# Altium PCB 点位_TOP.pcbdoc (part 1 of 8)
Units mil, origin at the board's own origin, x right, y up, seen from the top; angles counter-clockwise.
Board outline 5129 x 4161 mil, 8 copper layers (Top Layer, GND1, 内层2, VCC, 内层4, Inner5, GND2, Bottom Layer); 288 components, 452 nets, 2040 pads, 1119 vias.
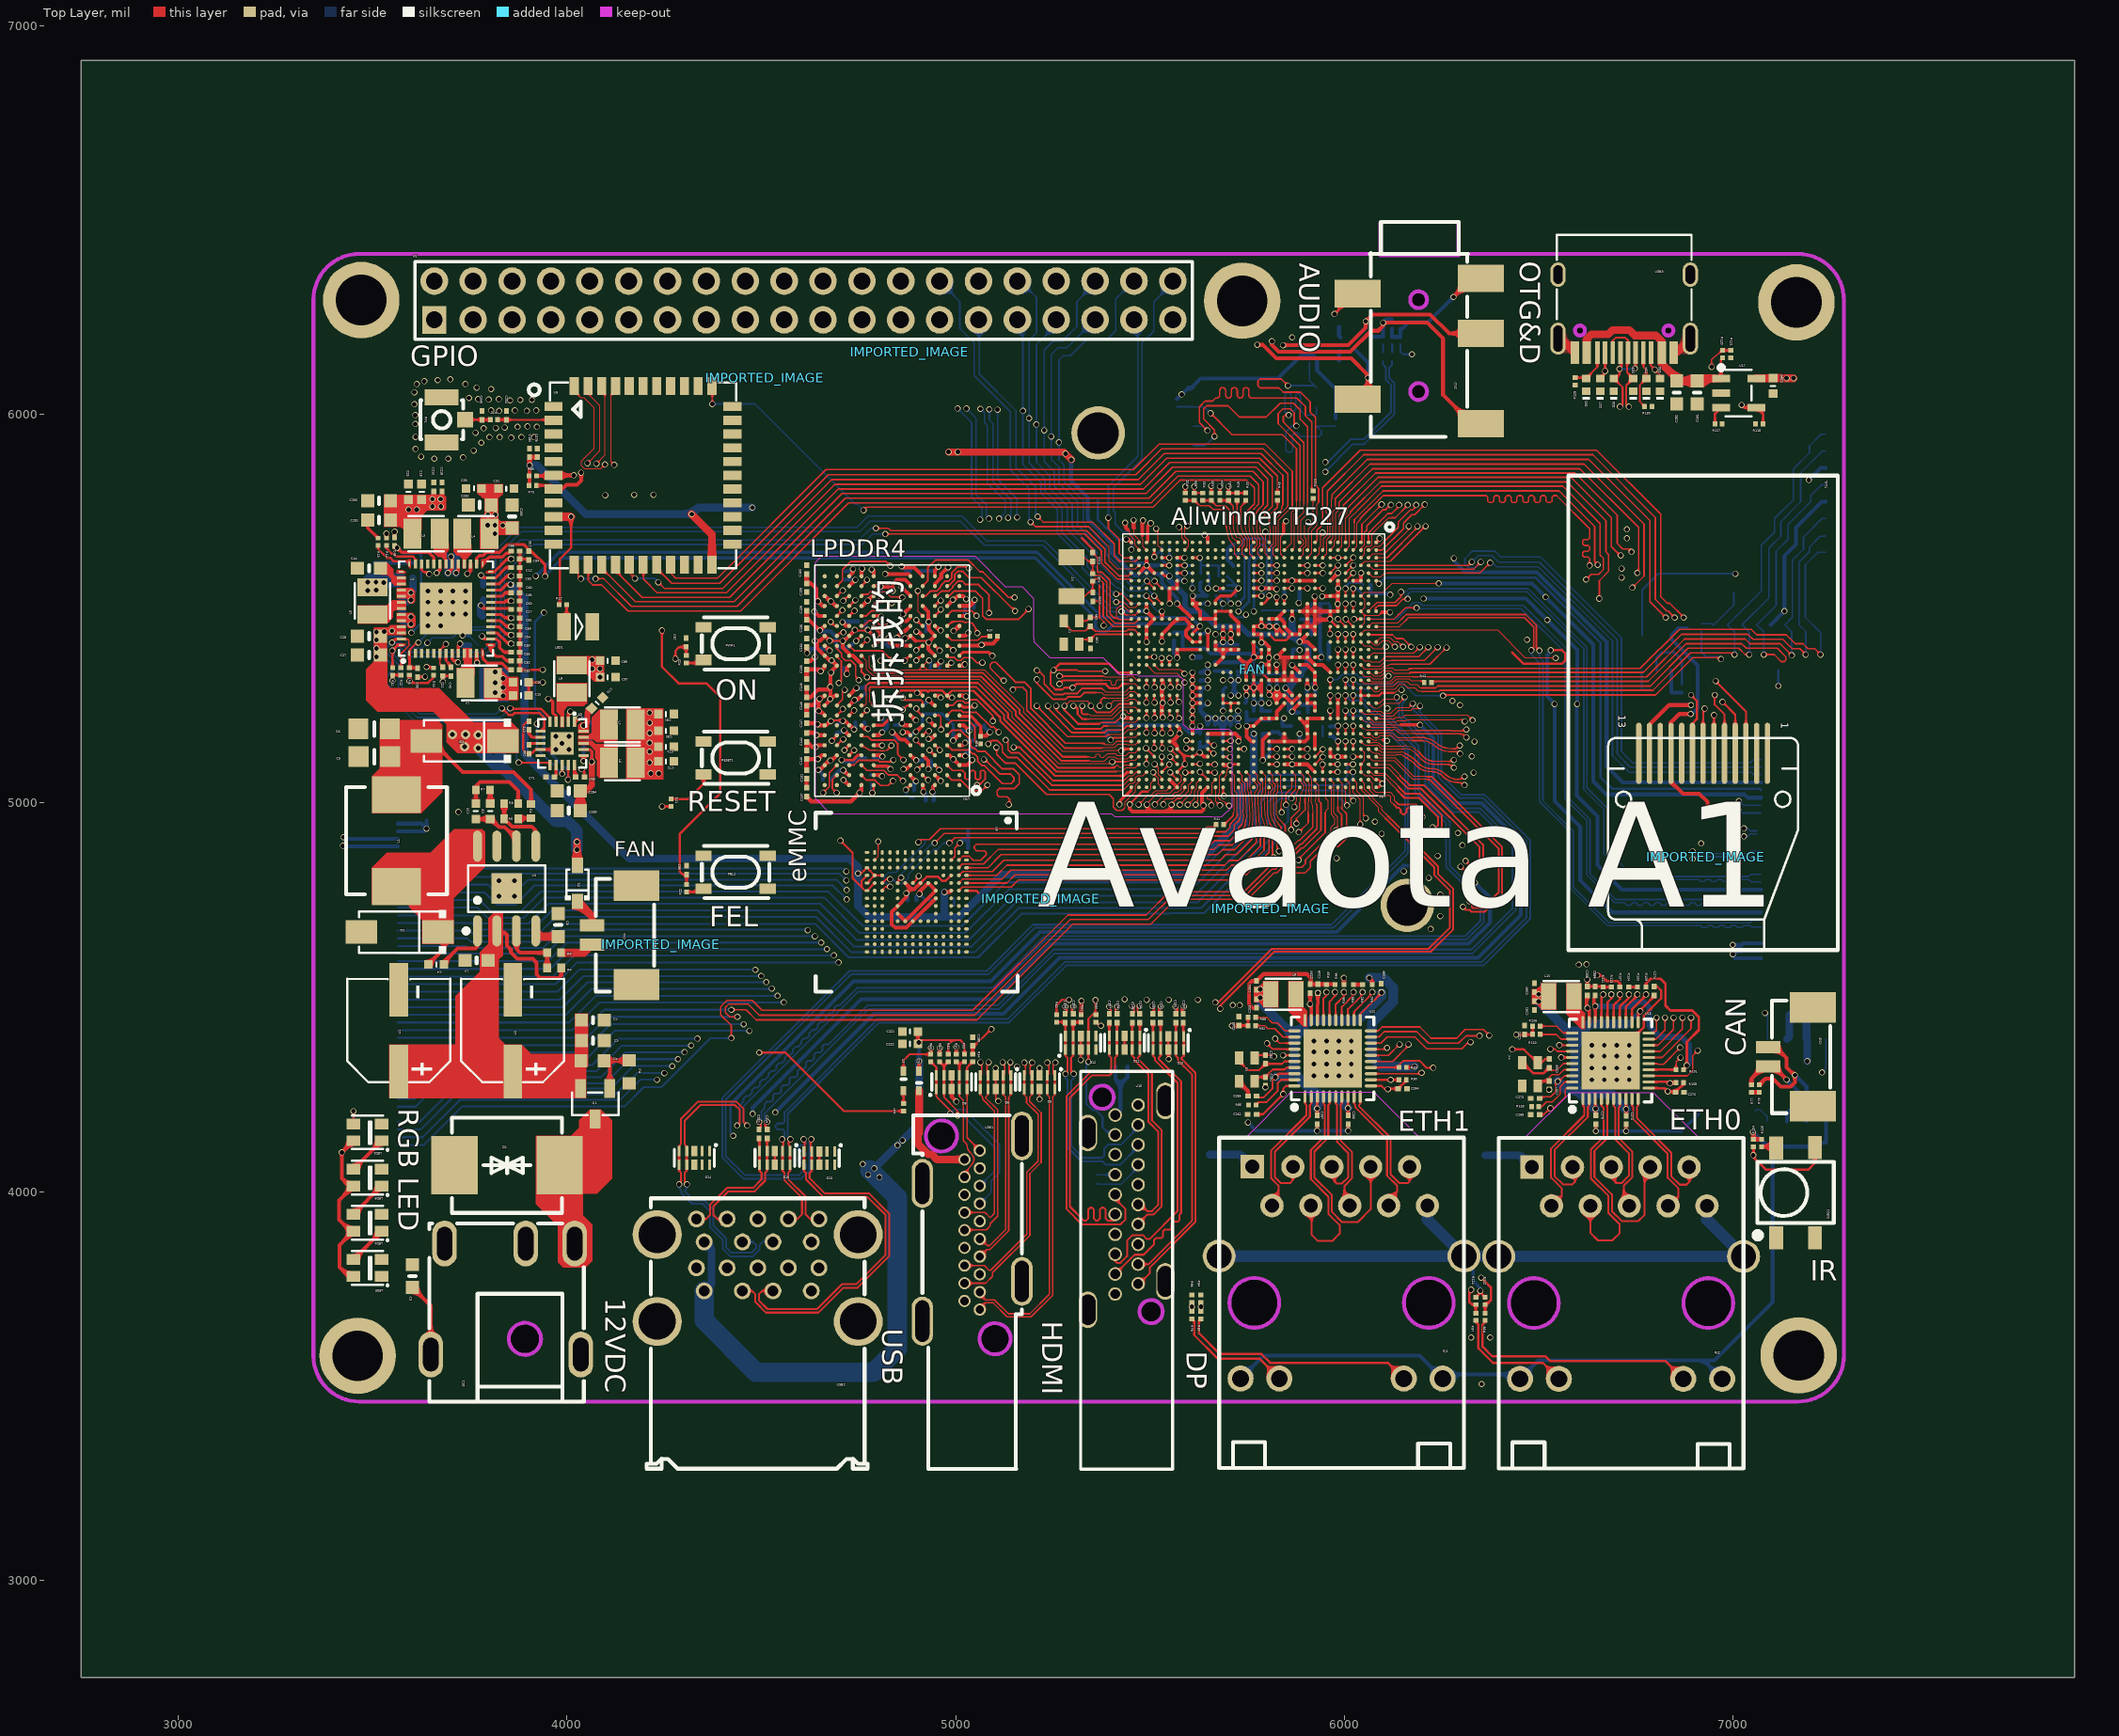
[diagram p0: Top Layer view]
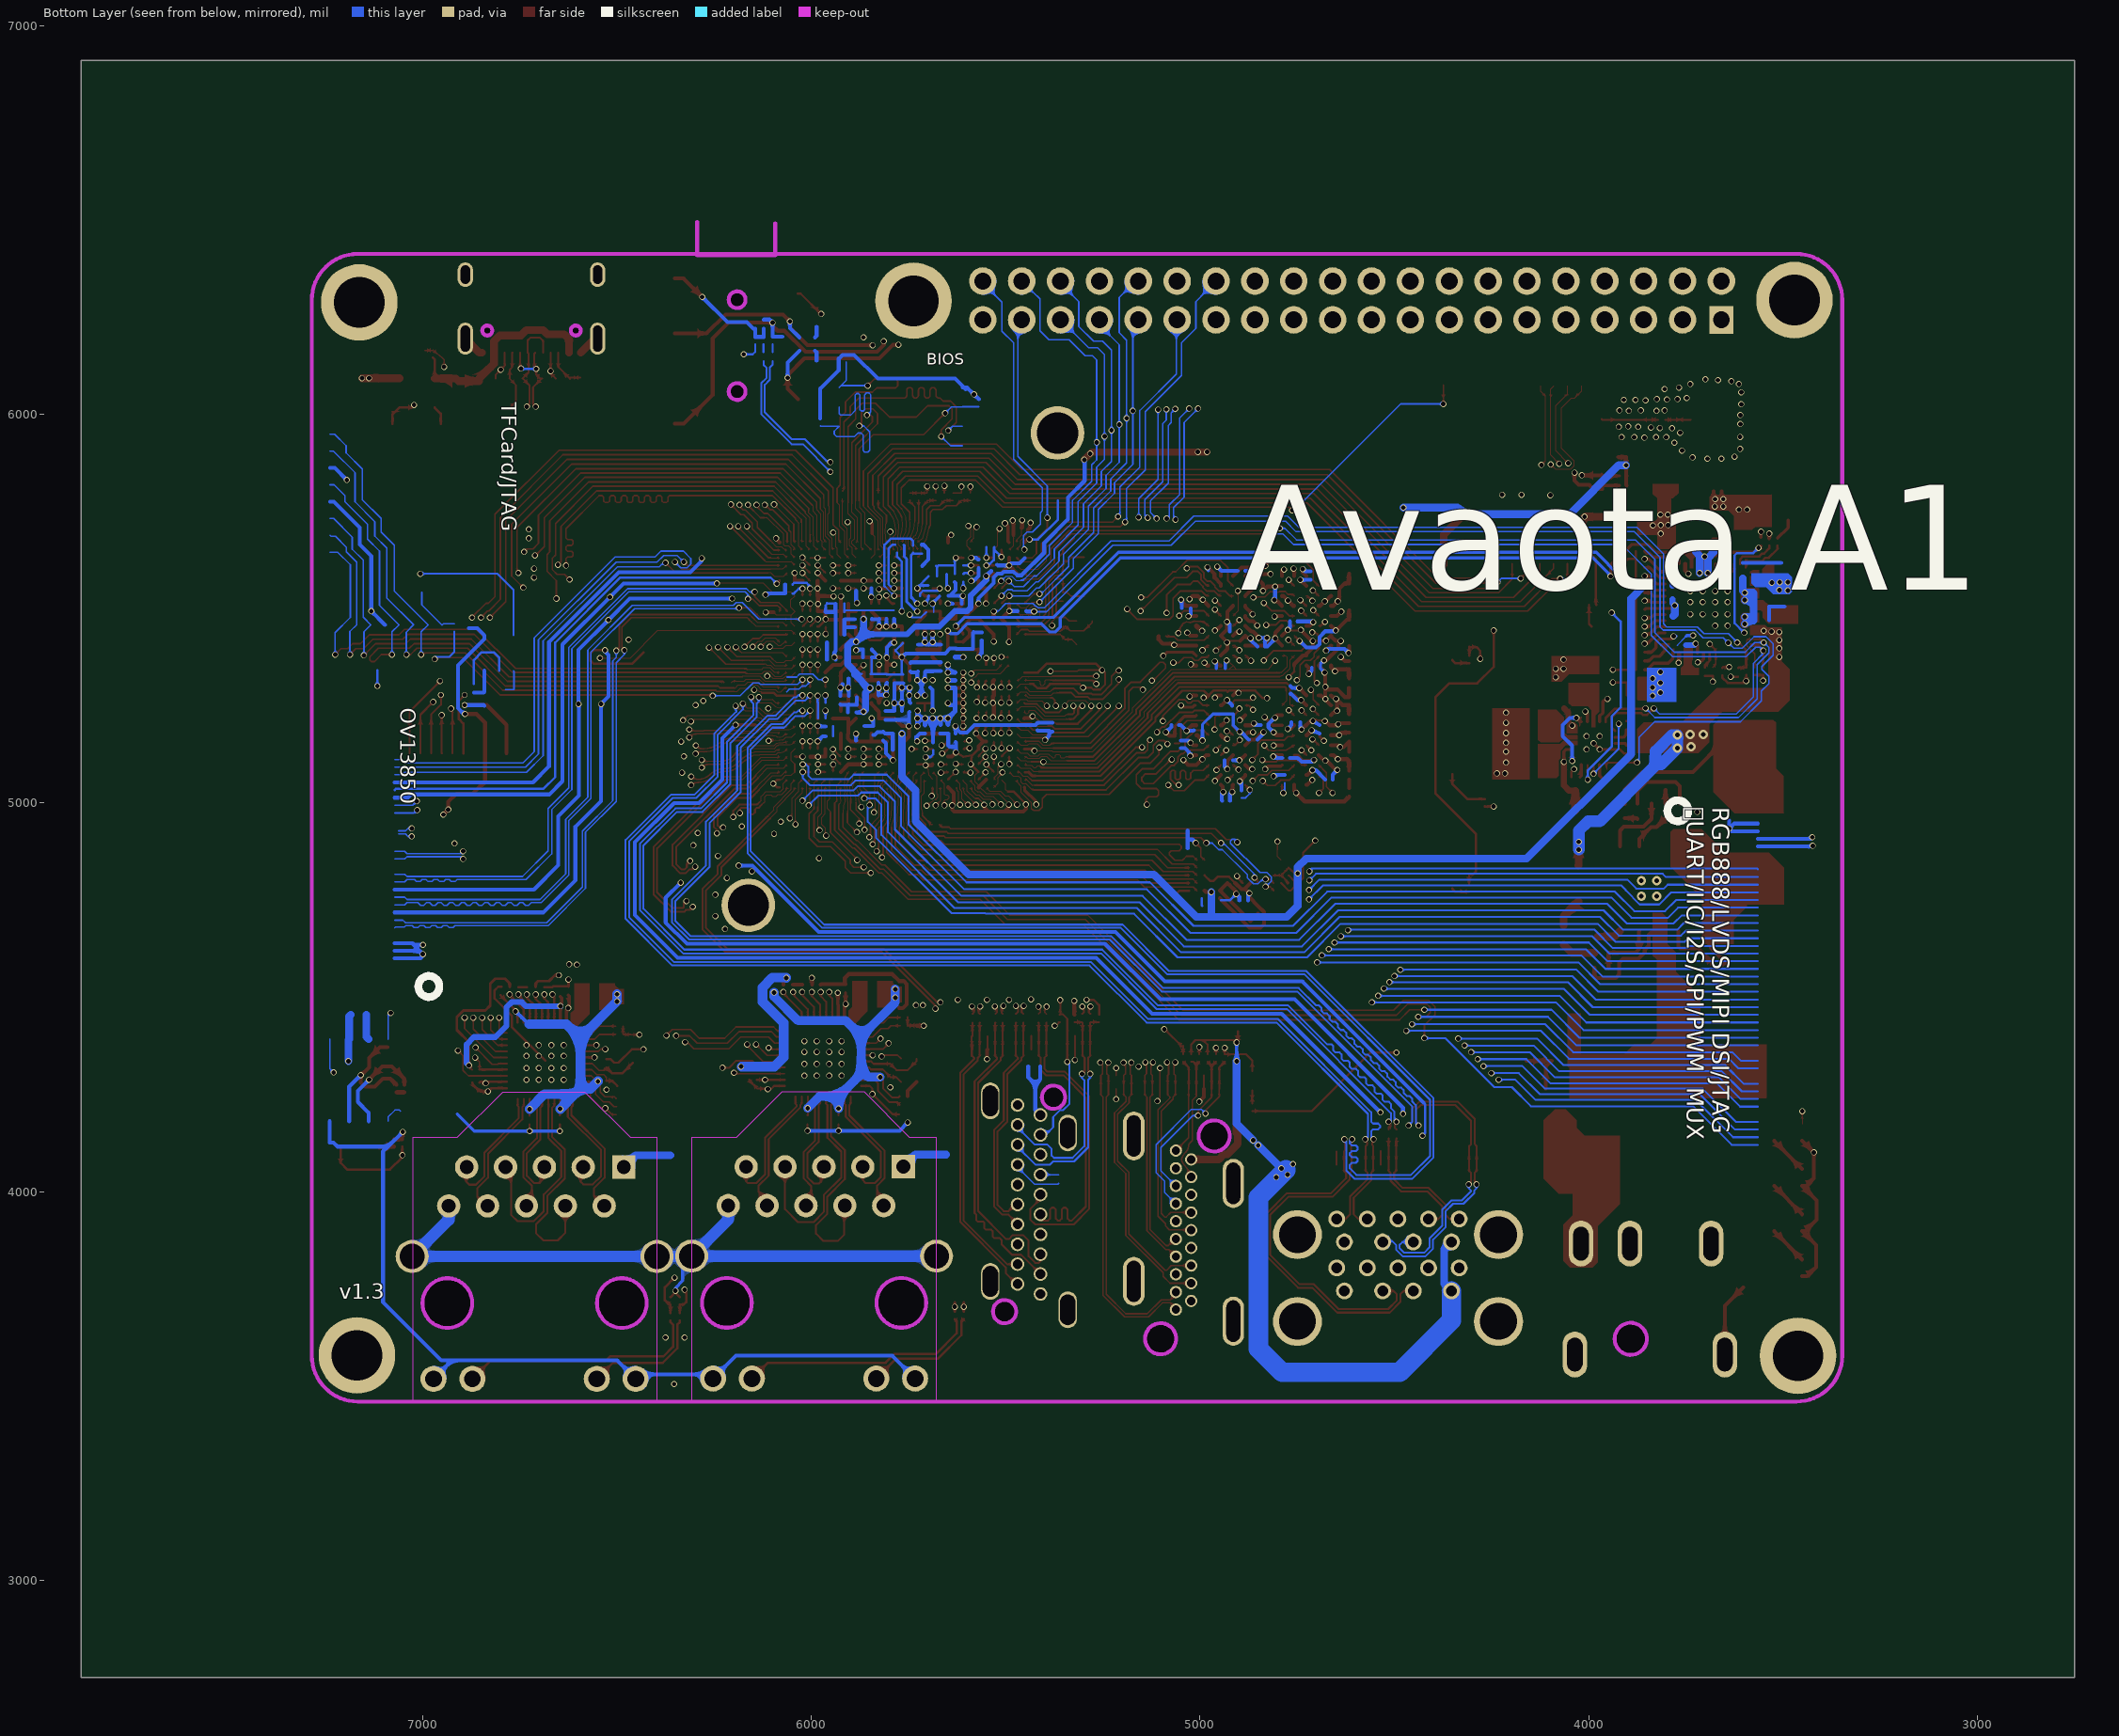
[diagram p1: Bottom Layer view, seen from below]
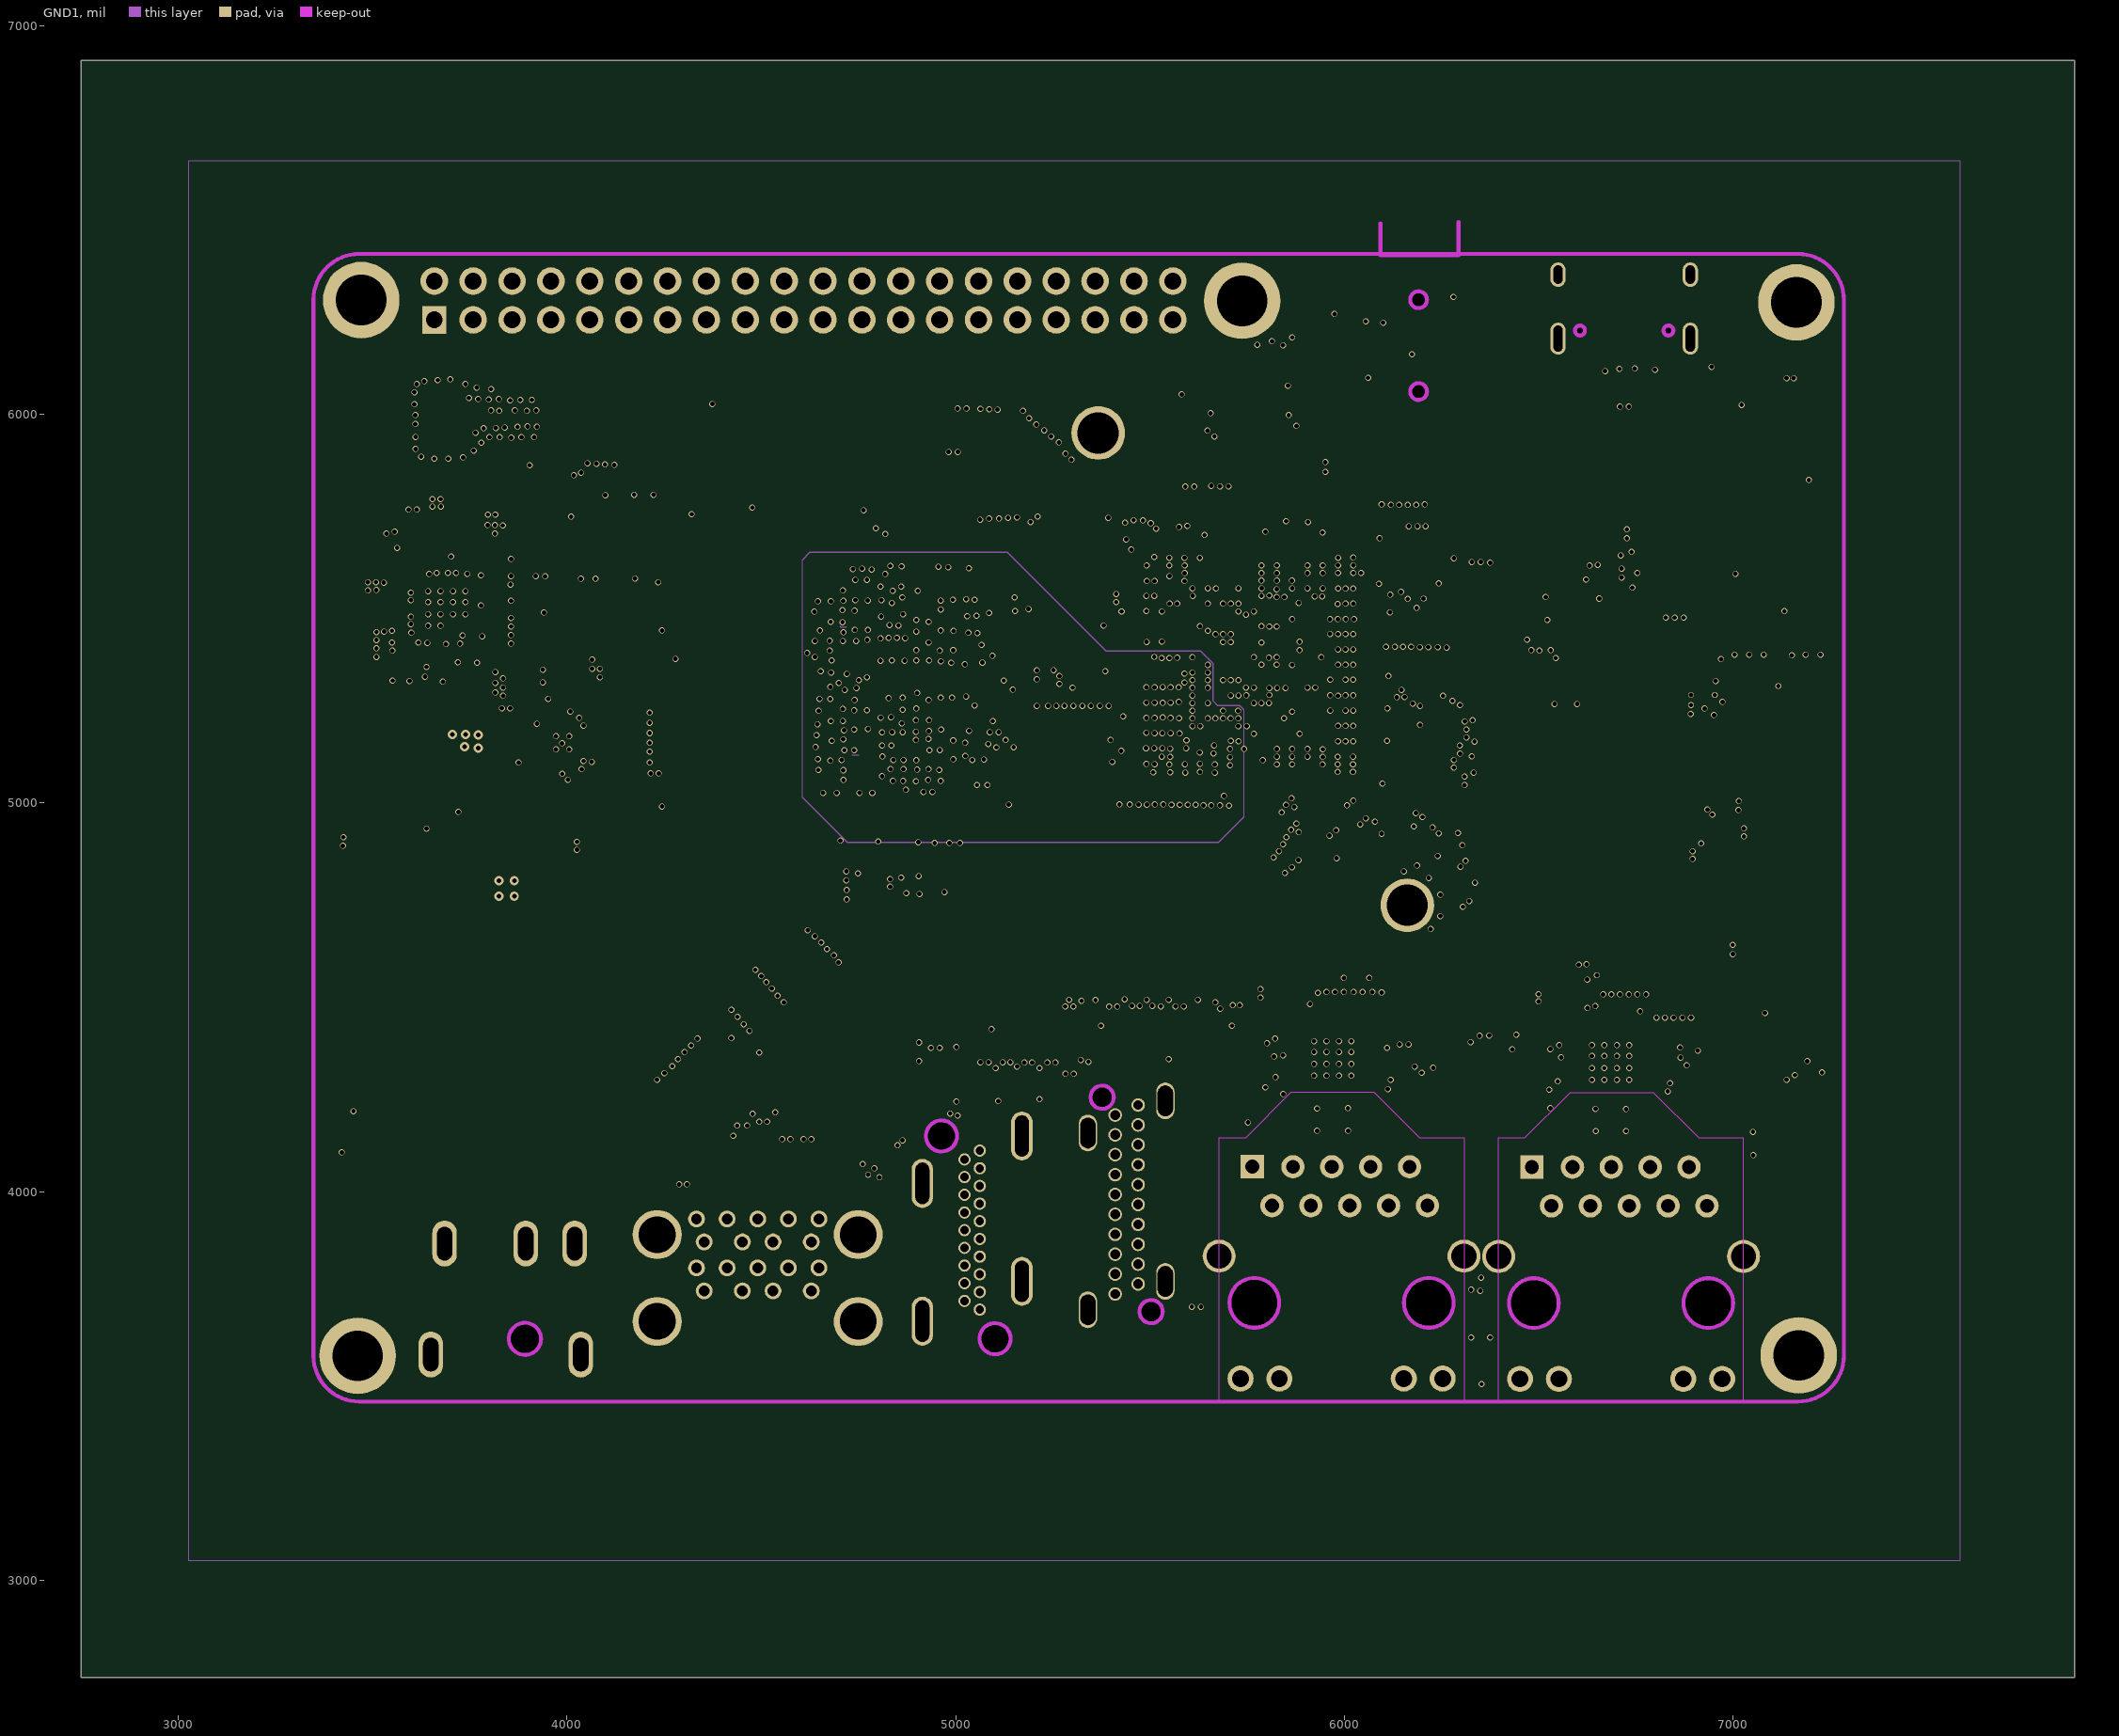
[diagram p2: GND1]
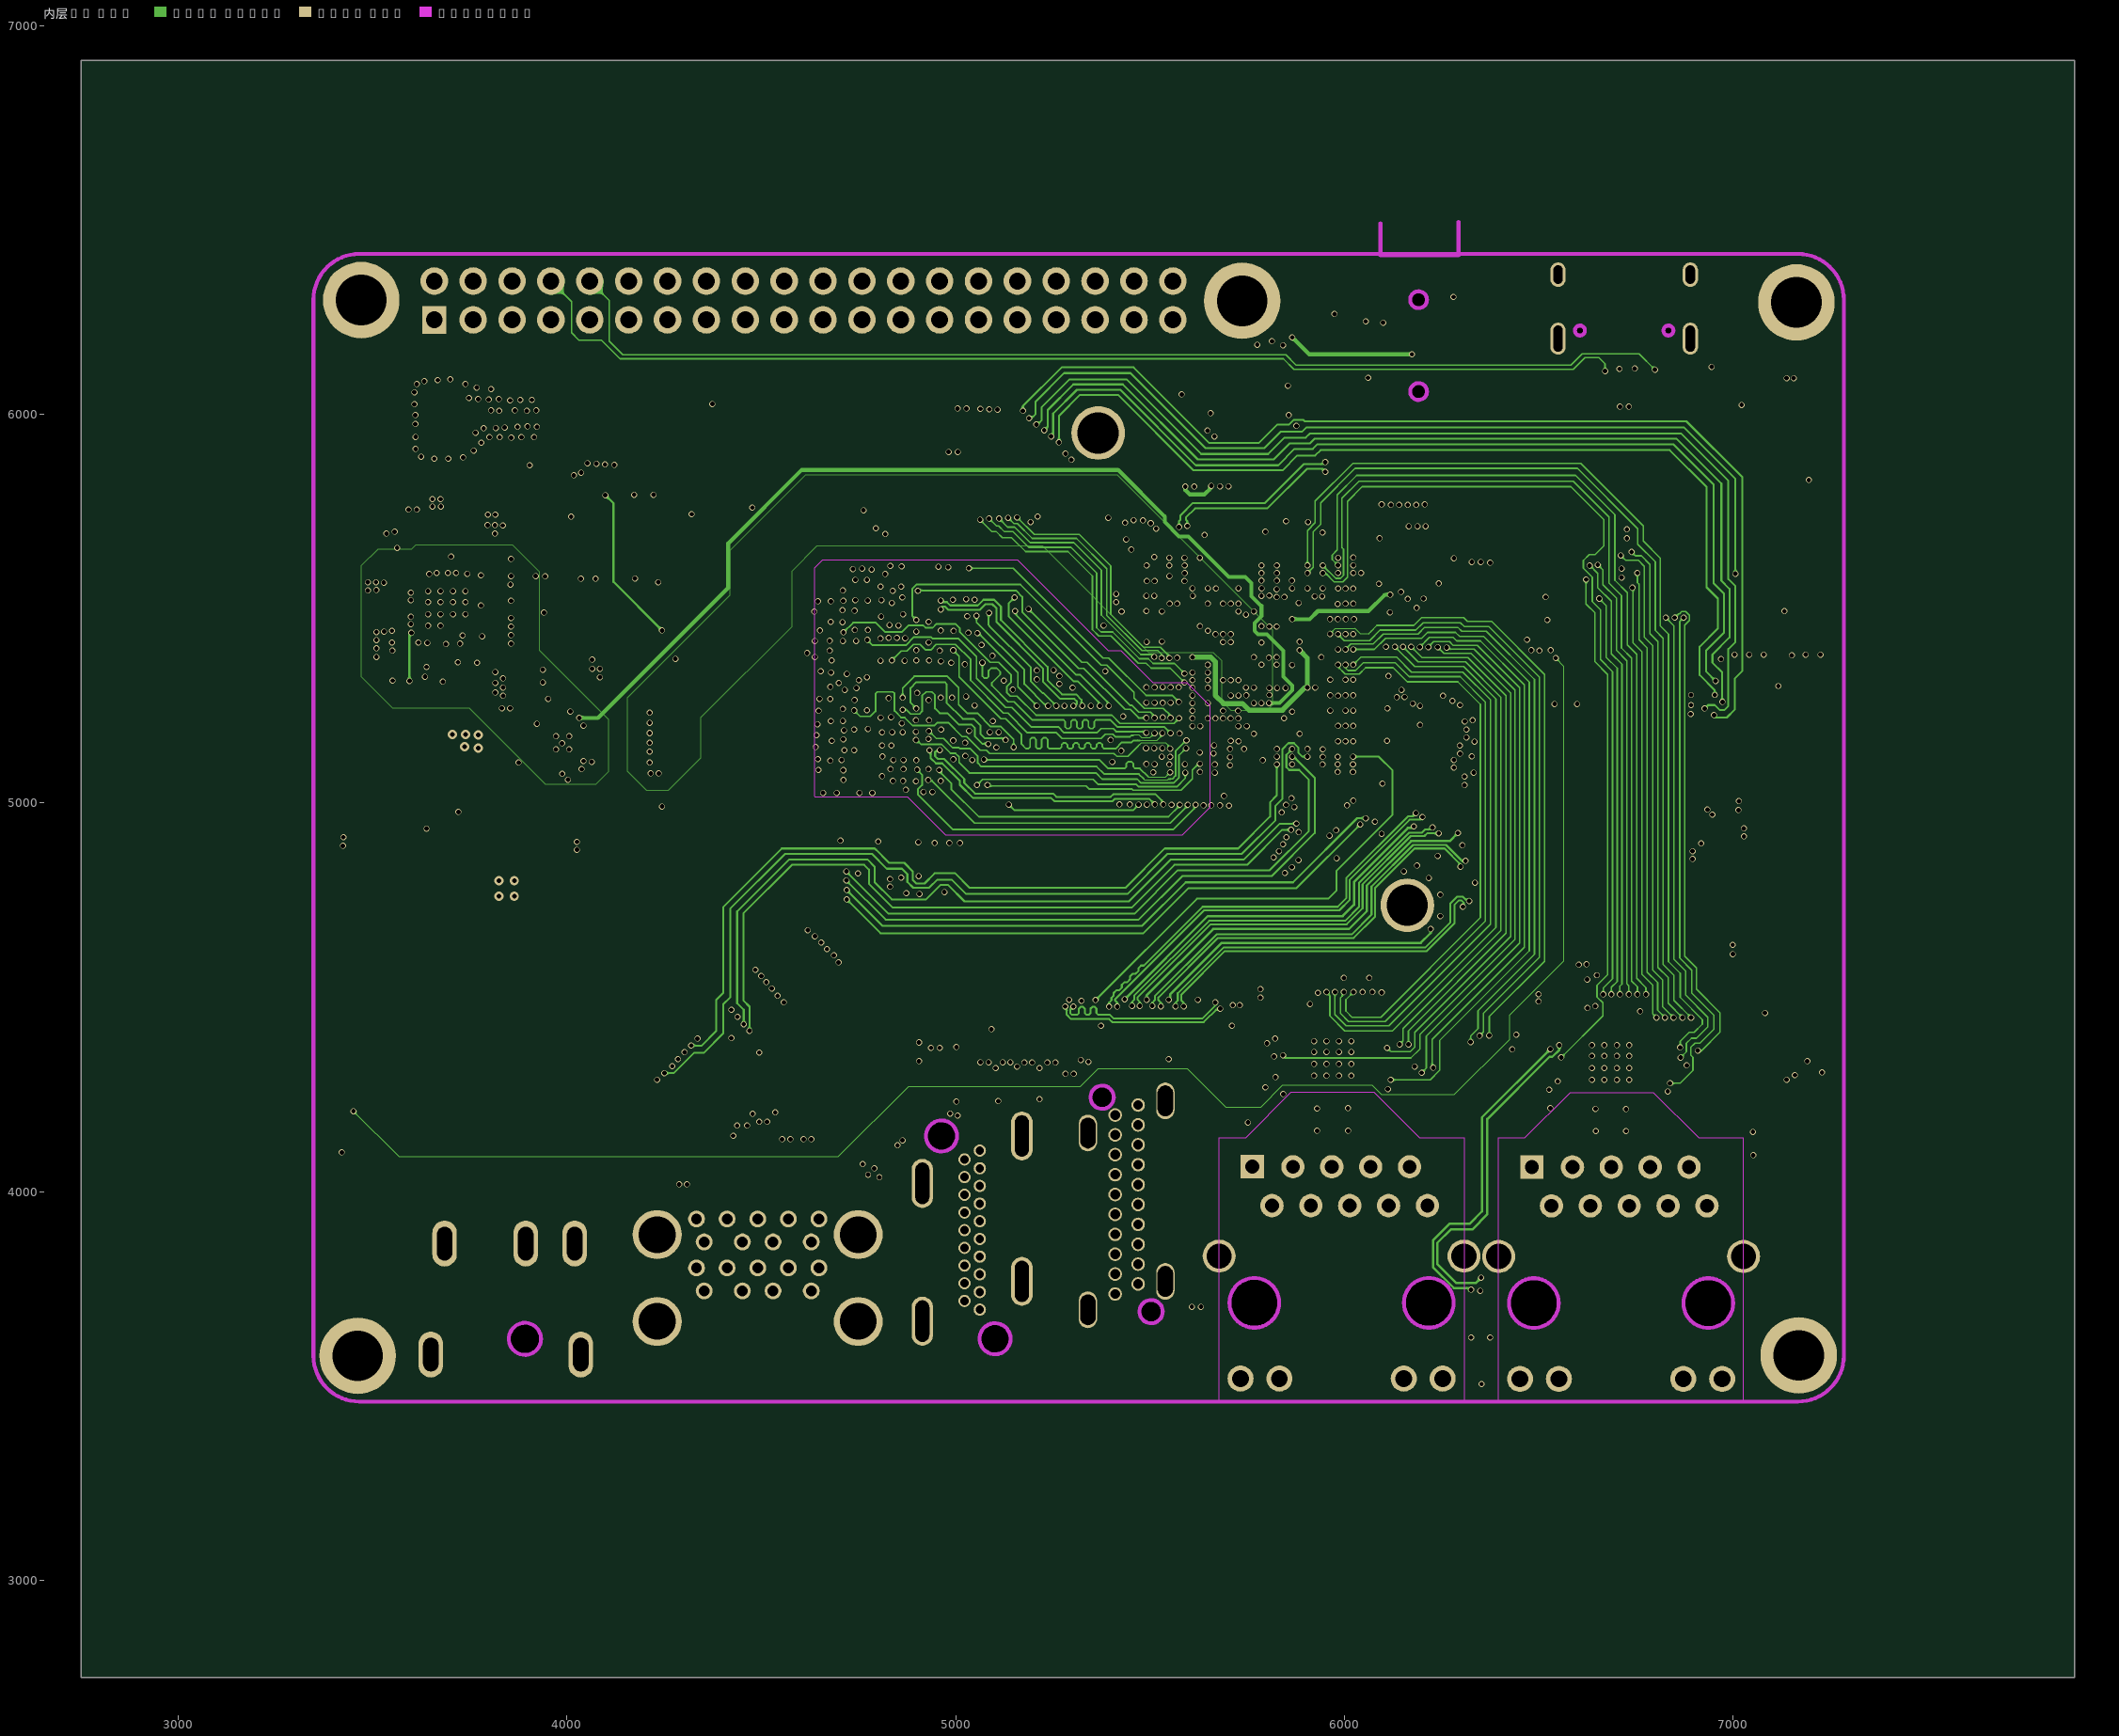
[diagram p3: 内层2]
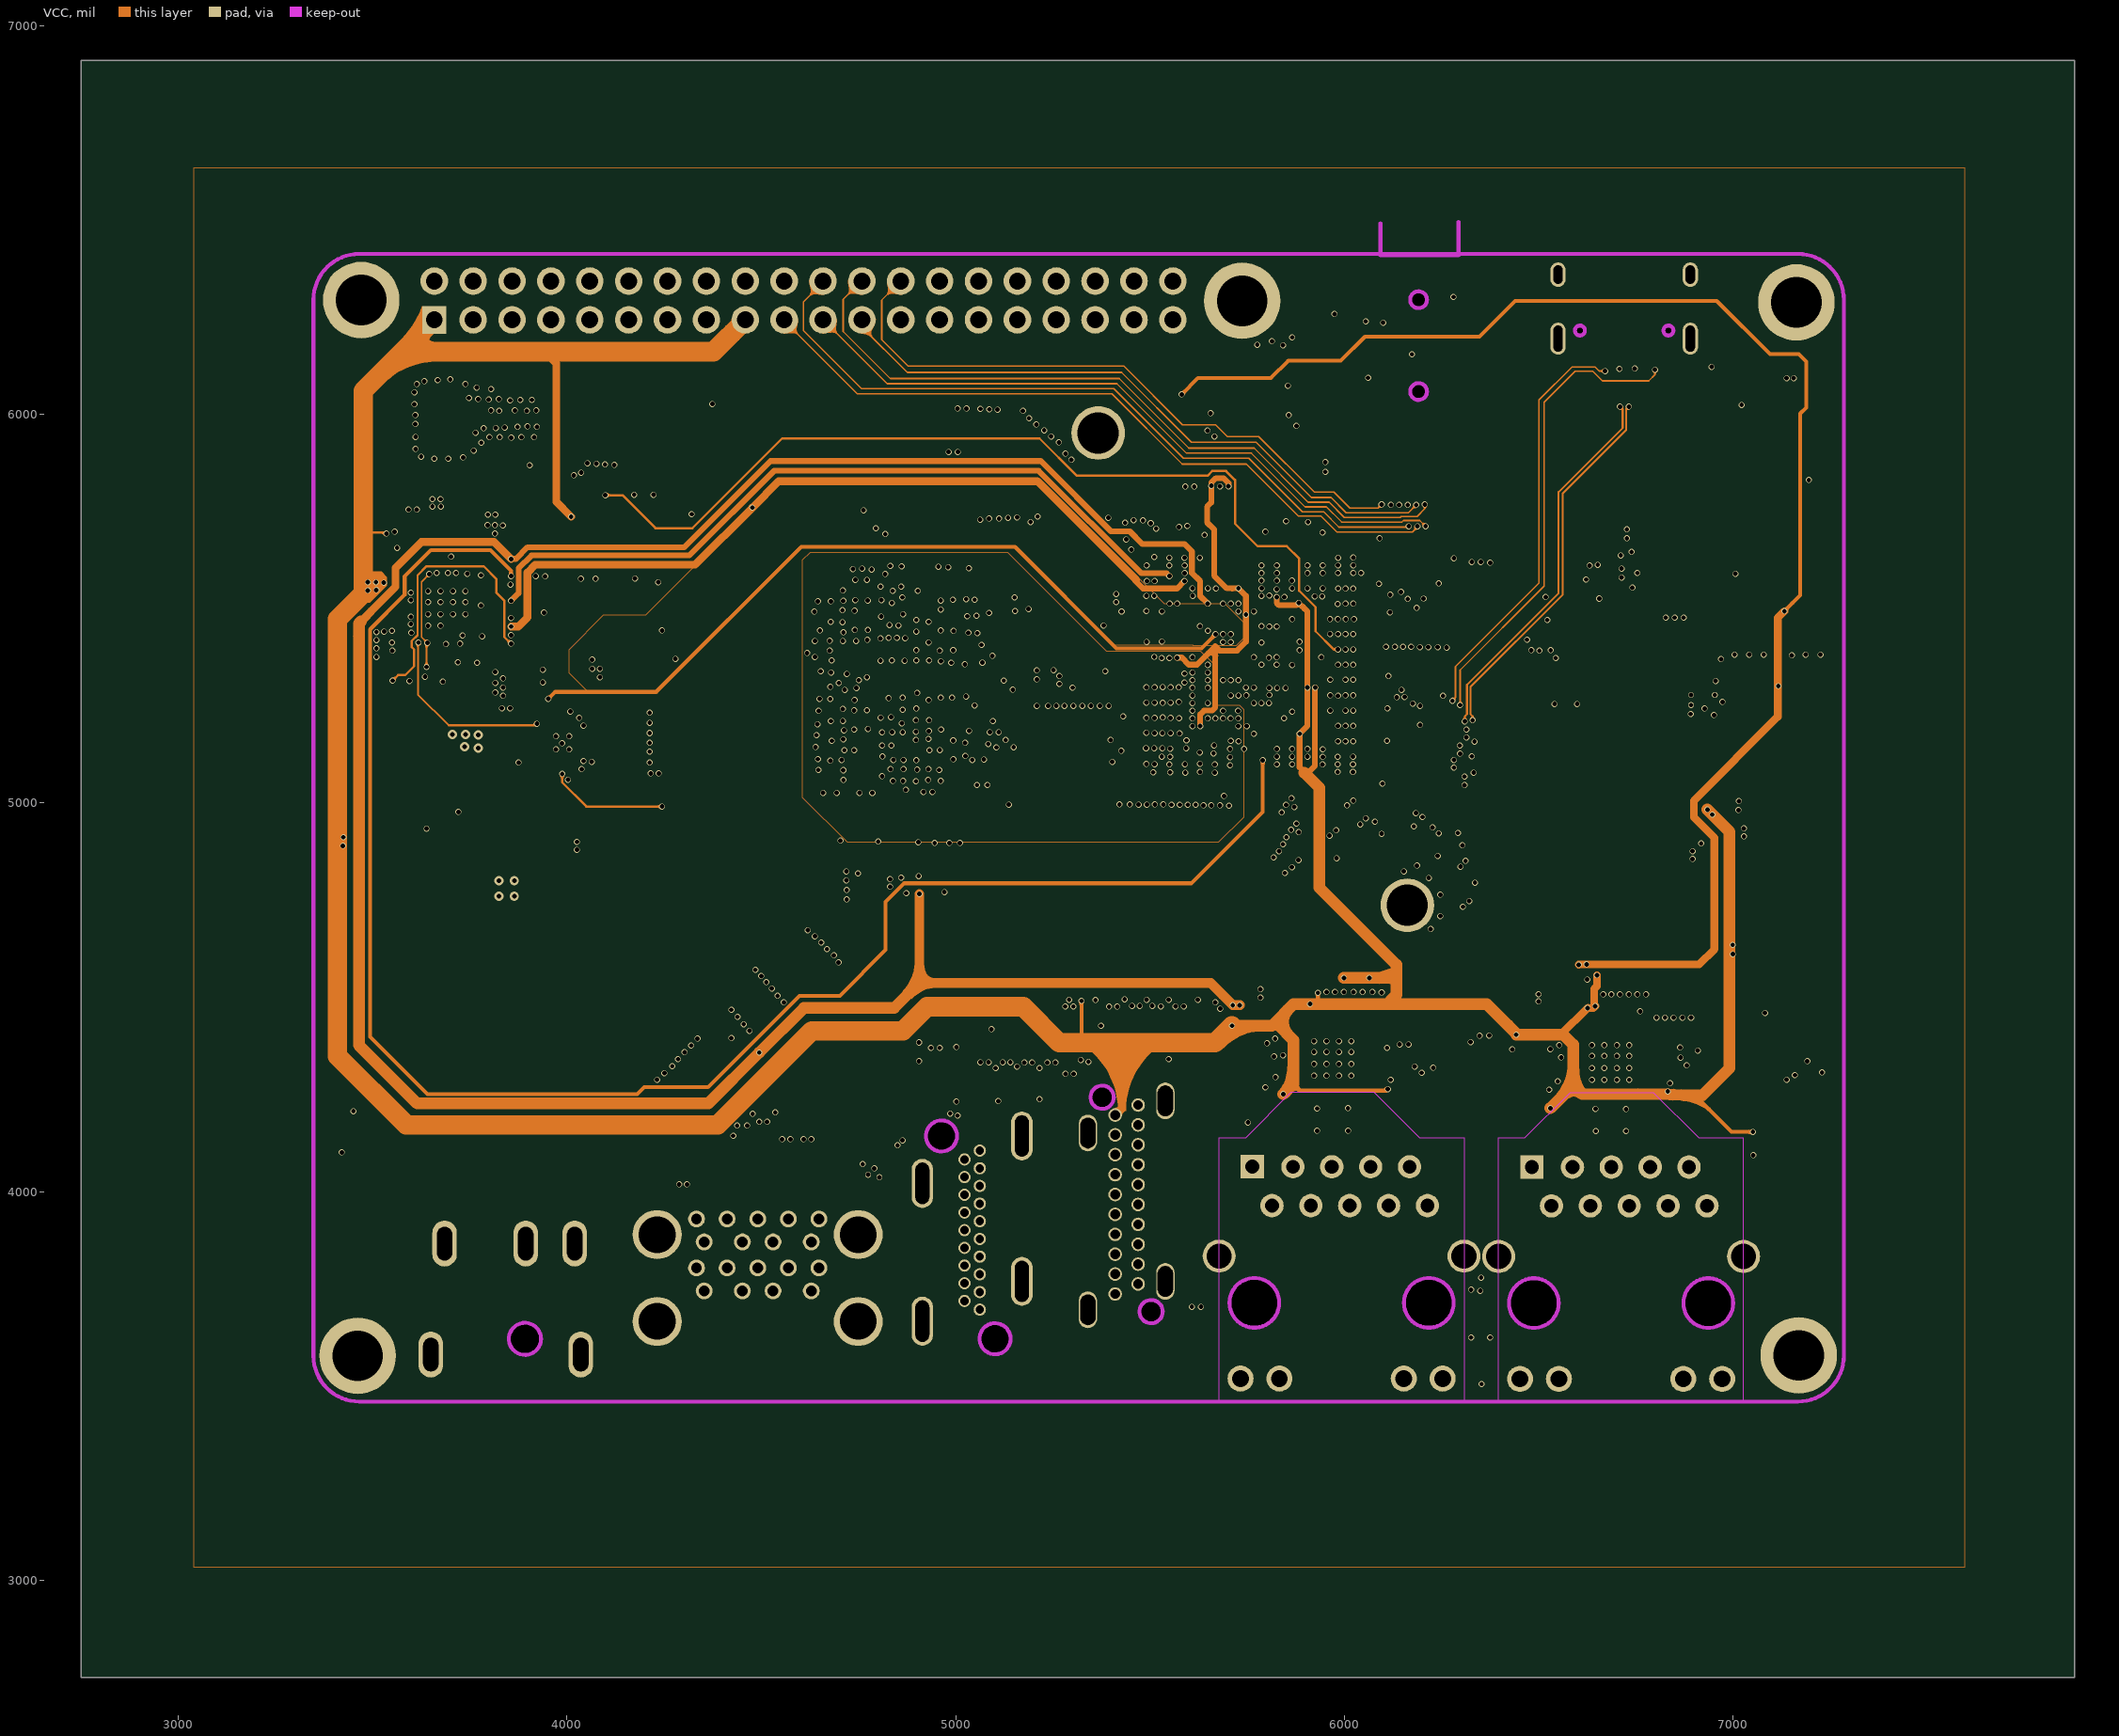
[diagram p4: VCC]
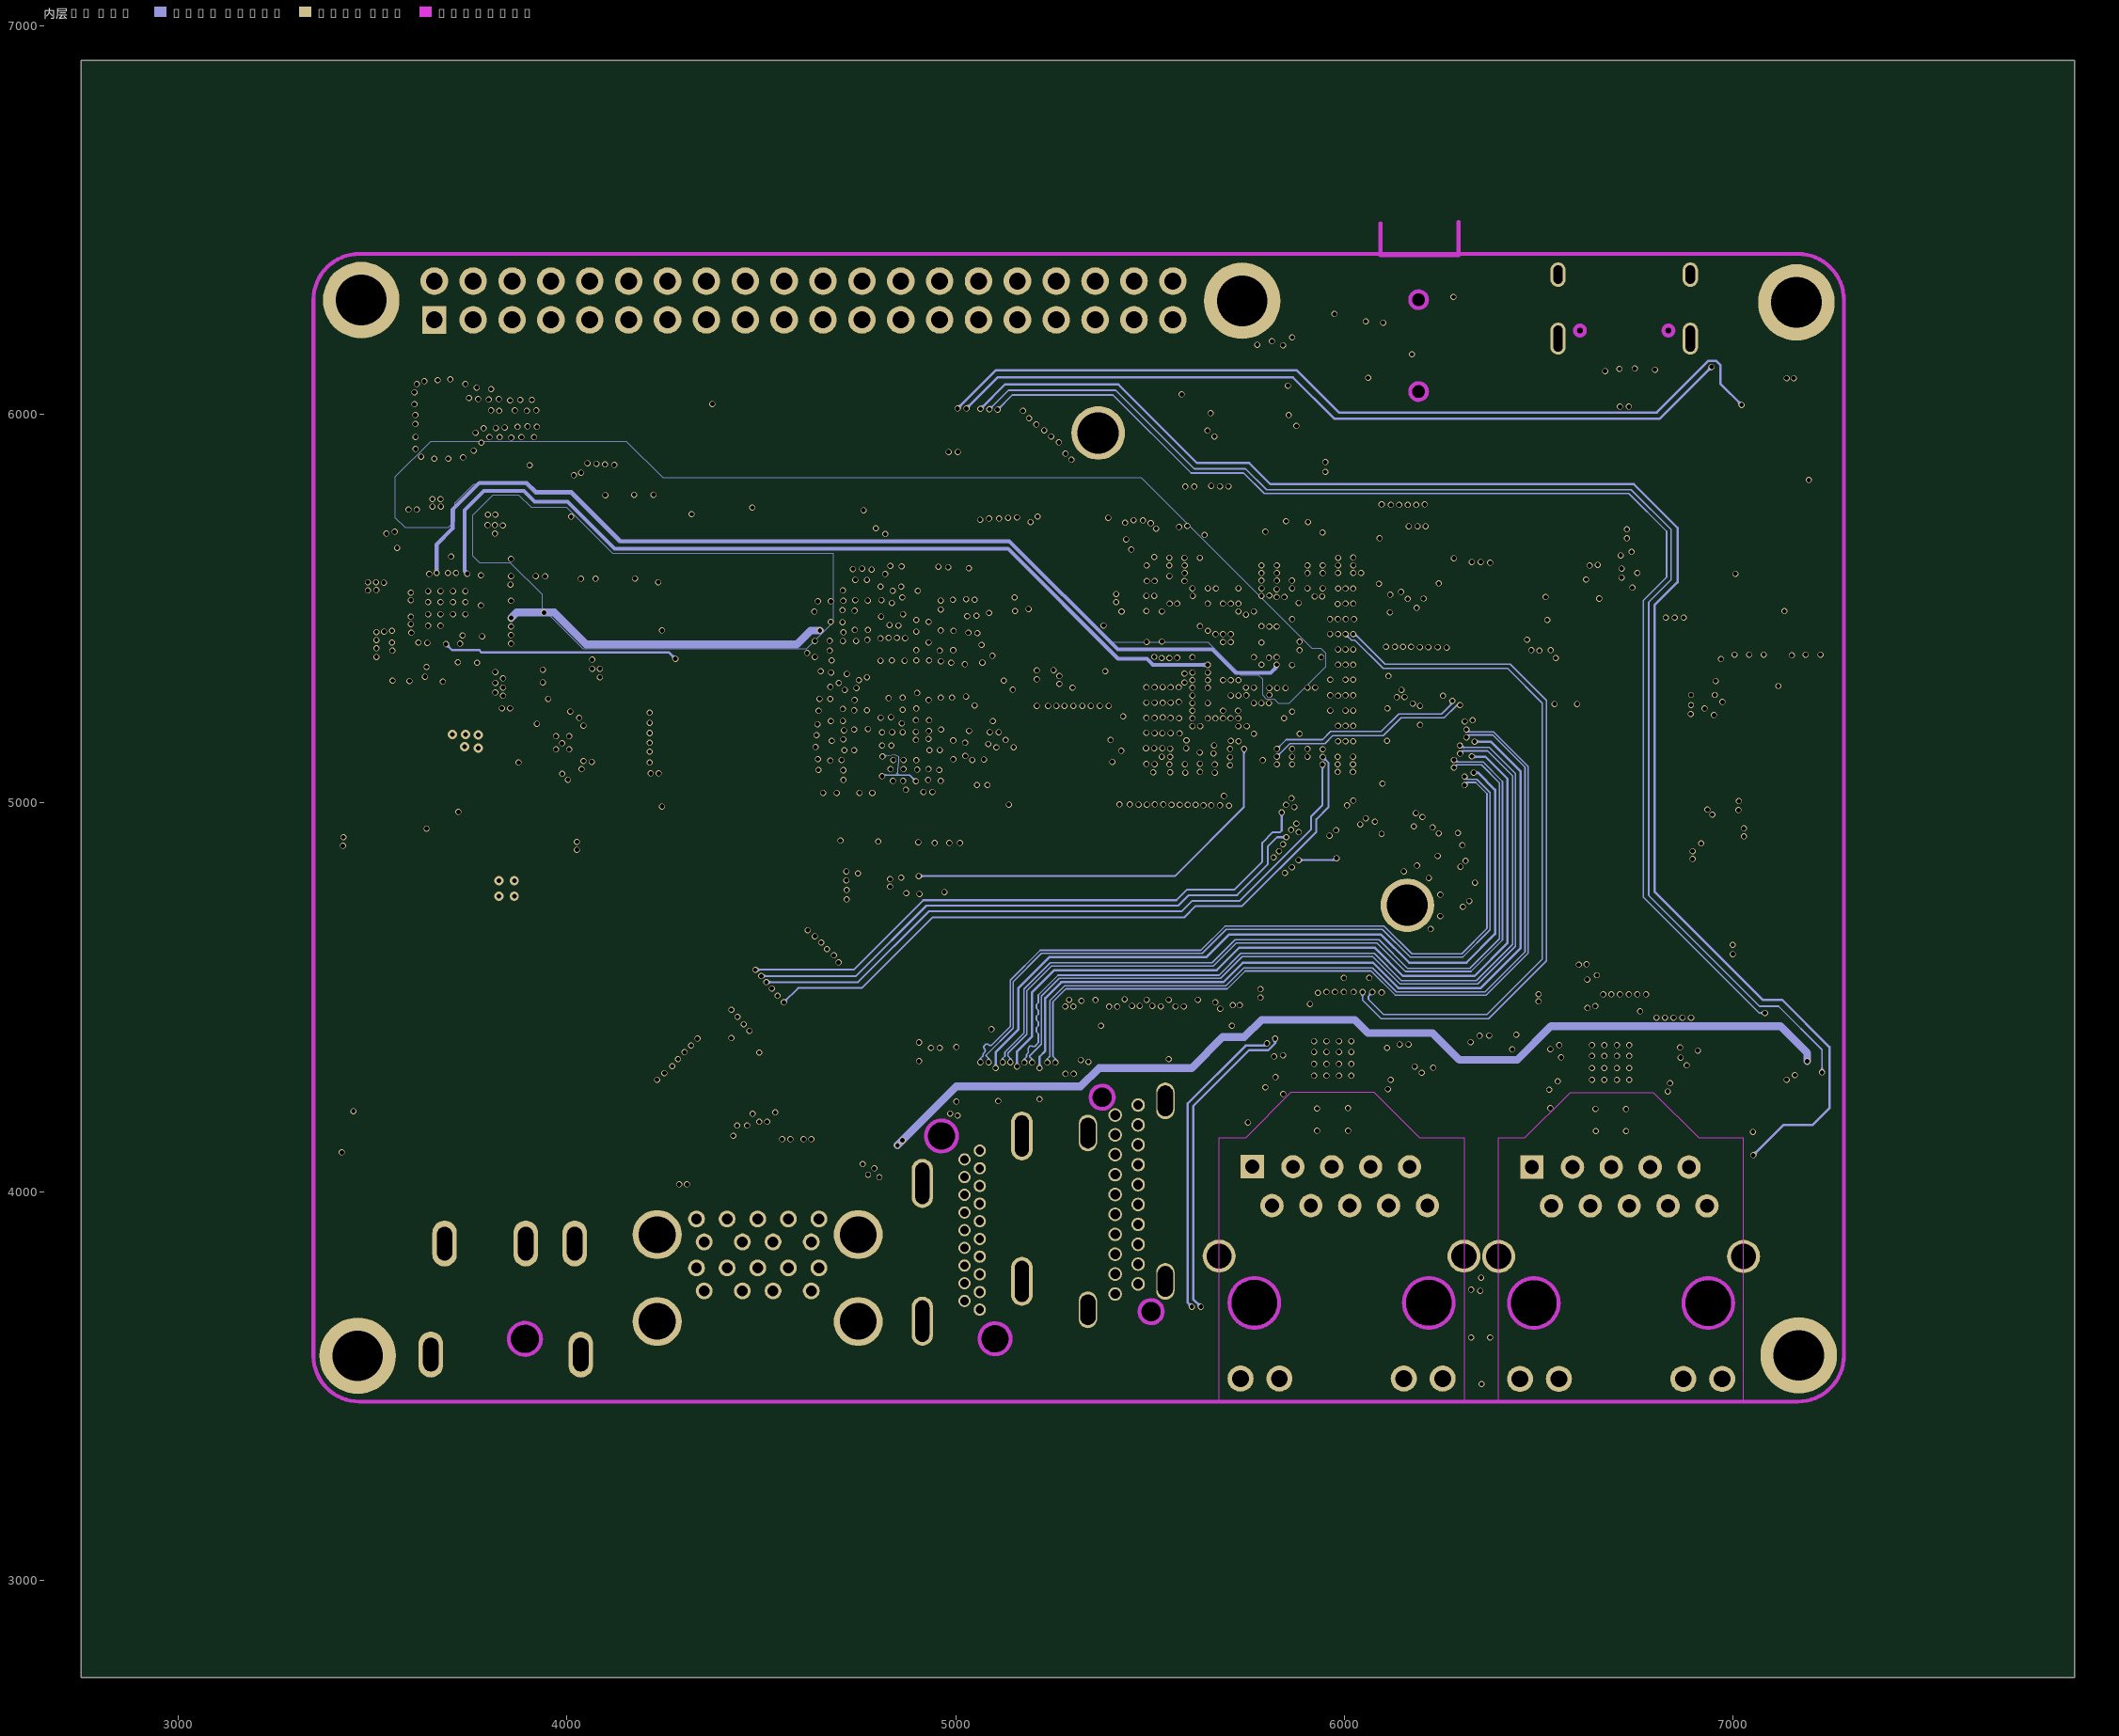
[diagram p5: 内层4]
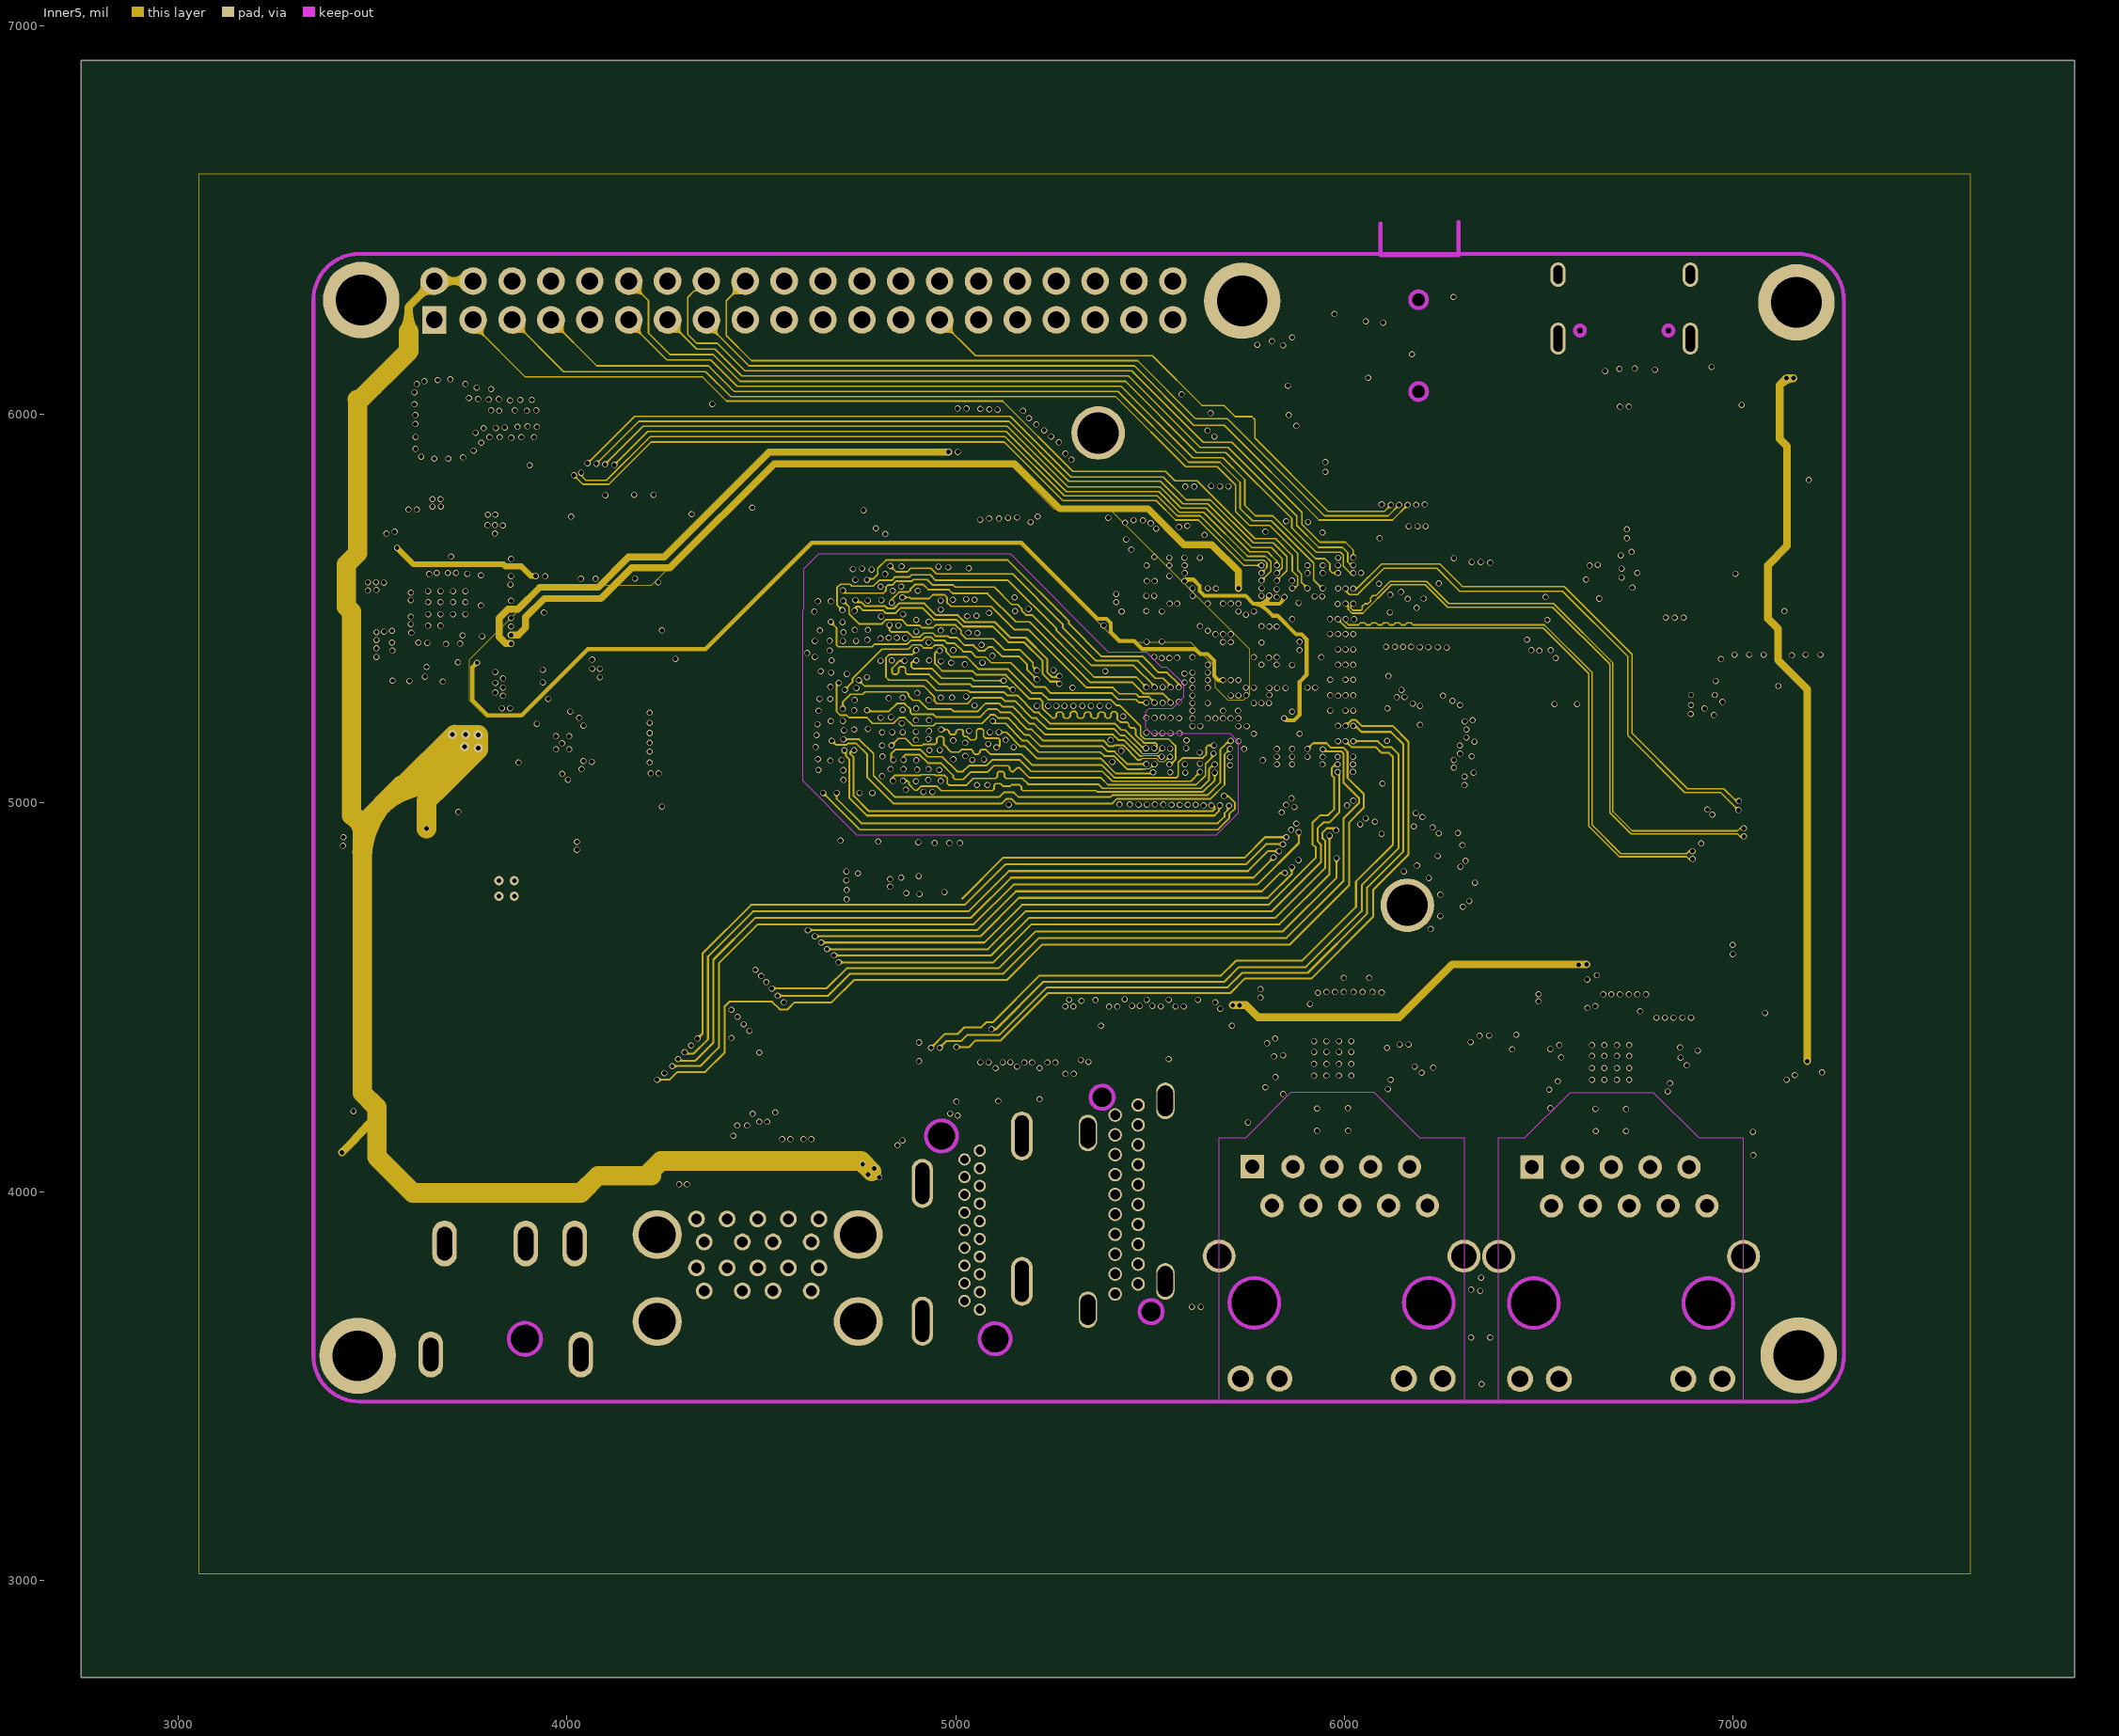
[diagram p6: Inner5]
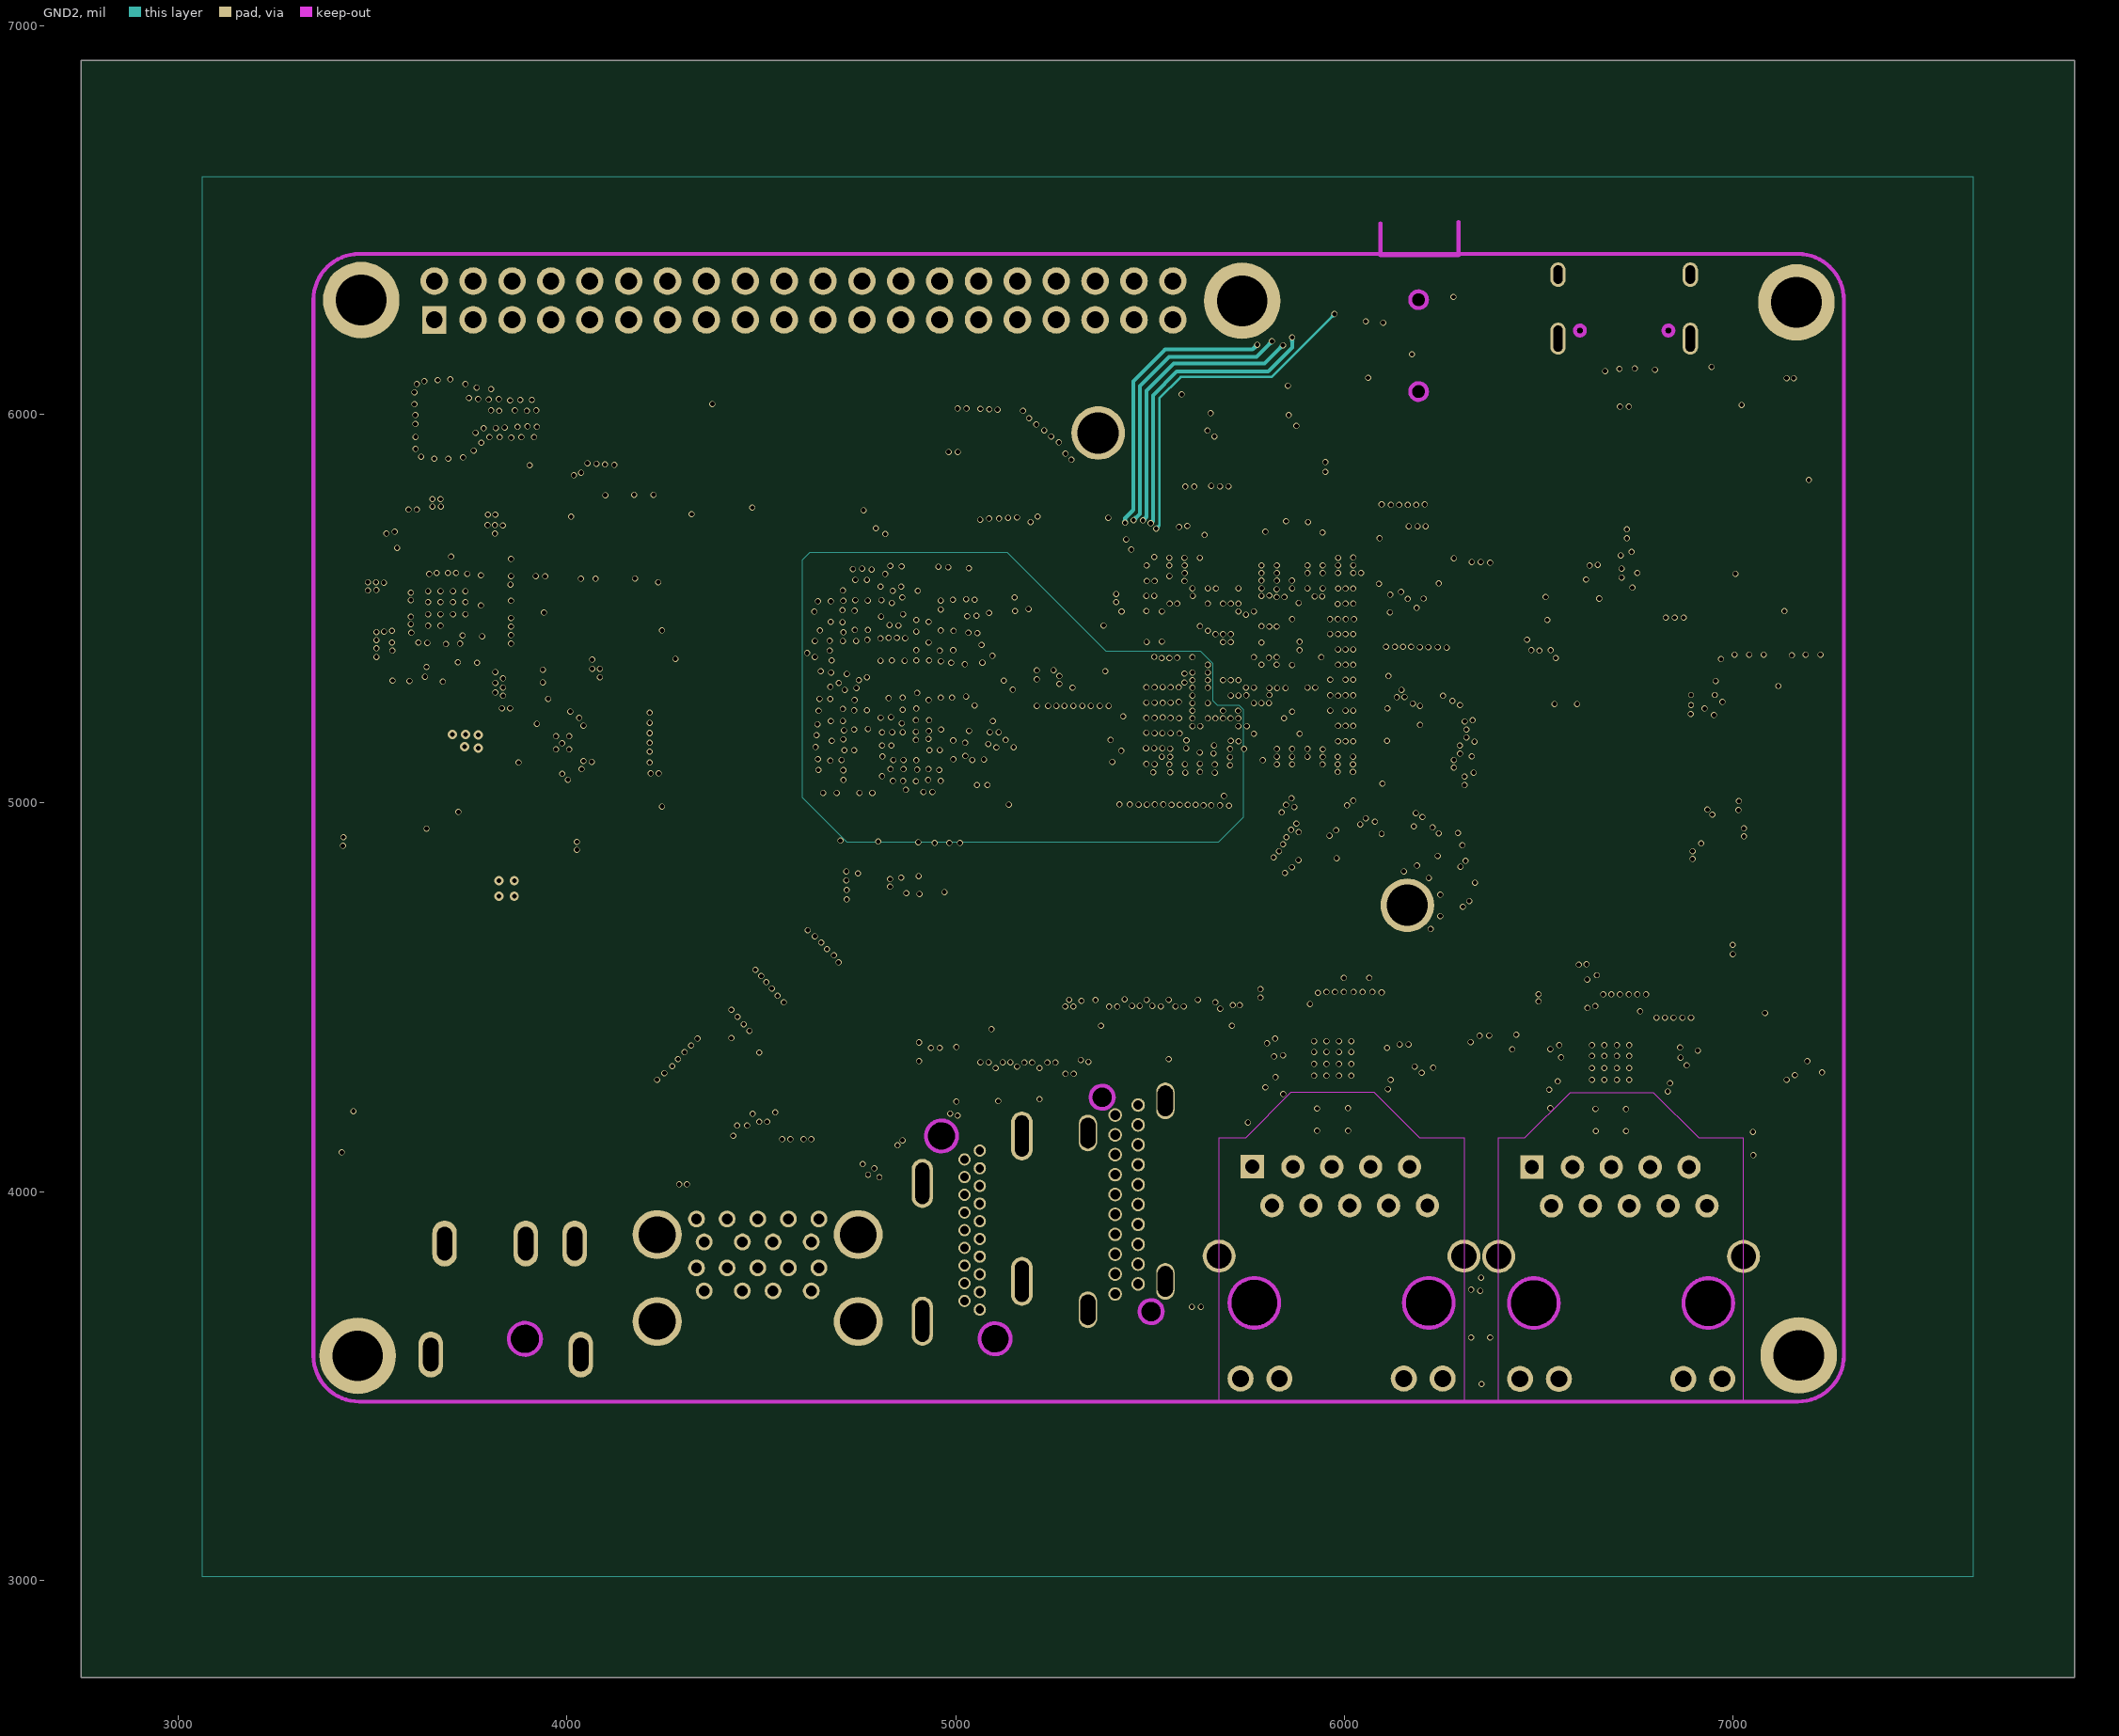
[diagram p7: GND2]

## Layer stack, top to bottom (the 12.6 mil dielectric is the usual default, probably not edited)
Top Layer: signal copper (thickness not stored)
Dielectric: dielectric 12.6, FR-4, Dk 4.8
GND1: signal copper (thickness not stored)
Dielectric: dielectric 12.6, FR-4, Dk 4.8
内层2: signal copper (thickness not stored)
Dielectric: dielectric 12.6, FR-4, Dk 4.8
VCC: signal copper (thickness not stored)
Dielectric: dielectric 12.6, FR-4, Dk 4.8
内层4: signal copper (thickness not stored)
Dielectric: dielectric 12.6, FR-4, Dk 4.8
Inner5: signal copper (thickness not stored)
Dielectric: dielectric 12.6, FR-4, Dk 4.8
GND2: signal copper (thickness not stored)
Dielectric: dielectric 12.6, FR-4, Dk 4.8
Bottom Layer: signal copper (thickness not stored)

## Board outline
7879,2750 2750,2750 2750,6911 7879,6911

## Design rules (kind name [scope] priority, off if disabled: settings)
Clearance safeClearance [All] p1: gap=7 ignorepadtopadclearanceinfootprint=FALSE except(3.5: Track-Track Track-SMDPad SMDPad-SMDPad Track-THPad SMDPad-THPad THPad-THPad Track-Via SMDPad-Via THPad-Via Via-Via Track-Fill SMDPad-Fill THPad-Fill Via-Fill Fill-Fill Track-Region SMDPad-Region THPad-Region Via-Region Fill-Region Region-Region Track-Poly SMDPad-Poly THPad-Poly Via-Poly Fill-Poly Region-Poly Poly-Poly Track-Text SMDPad-Text THPad-Text Via-Text Fill-Text Region-Text Poly-Text Text-Text SMDPad-Sheet THPad-Sheet Track-Hole SMDPad-Hole THPad-Hole Via-Hole Fill-Hole Region-Hole Poly-Hole Text-Hole Sheet-Hole; 11.8: Track-Sheet Via-Sheet Fill-Sheet Region-Sheet Poly-Sheet Text-Sheet)
DiffPairsRouting differentialPair [All] p1: maxuncoupledlength=50 minlimit=0 maxlimit=4 mostfreqgap=4 toplayer_minwidth=3 toplayer_prefwidth=10 toplayer_maxwidth=100 bottomlayer_minwidth=3 bottomlayer_prefwidth=10 bottomlayer_maxwidth=100 midlayer1_minwidth=3 midlayer1_prefwidth=10 midlayer1_maxwidth=100 midlayer2_minwidth=3 midlayer2_prefwidth=10 midlayer2_maxwidth=100 midlayer3_minwidth=3 midlayer3_prefwidth=10 midlayer3_maxwidth=100 midlayer4_minwidth=3 midlayer4_prefwidth=10 midlayer4_maxwidth=100 midlayer5_minwidth=3 midlayer5_prefwidth=10 midlayer5_maxwidth=100 midlayer6_minwidth=3 midlayer6_prefwidth=10 midlayer6_maxwidth=100
PasteMaskExpansion pasteMaskExpansion [All] p1: expansion=0
PlaneConnect innerPlane [All] p1: planeconnectstyle=Relief reliefexpansion=20 reliefentries=4 reliefconductorwidth=10 reliefairgap=10
PolygonConnect copperRegion [All] p1: connectstyle=Relief reliefentries=4 reliefconductorwidth=10 polygonreliefangle="90 Angle" airgapwidth=10
PolygonConnect TBCopper [All] p1: connectstyle=Relief reliefentries=4 reliefconductorwidth=6 polygonreliefangle="90 Angle" airgapwidth=6
PolygonConnect DRAMCopper [All] p1: connectstyle=Relief reliefentries=4 reliefconductorwidth=4 polygonreliefangle="90 Angle" airgapwidth=4
RoutingVias viaSize [All] p1: viastyle="Through Hole" holewidth=7.9 minholewidth=7.9 maxholewidth=236.2 width=17.7 minwidth=15.7 maxwidth=393.7
SolderMaskExpansion solderMaskExpansion [All] p1: useseparateexpansions=TRUE expansion=4 expansionbottom=4
Width trackWidth [All] p1: maxlimit=100 minlimit=3 preferedwidth=4

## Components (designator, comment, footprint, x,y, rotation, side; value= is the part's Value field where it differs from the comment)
C1 "CAP_0603" C0603-NSK 4067,4441.54 r180 top
C2 "CAP_0603" C0603-NSK 4067,4388.54 r180 top
C3 "CAP_0603" C0603-NSK 3603,3783 r270 top
C4 "CAP_0402" c0402-nsk 3664,4585 r180 top
C5 "CAP_0805" "C0805 NSK" 3504.85,5119.18 r0 top
C6 "CAP_0805" "C0805 NSK" 3504.4,5190.55 r0 top
C7 "CAP_0603" C0603-NSK 3768,4595 r0 top
C8 "CAP_0603" C0603-NSK 3978,4686 r270 top
C9 "CAP_0402" c0402-nsk 3803,4979 r90 top
C10 "CAP_0402" c0402-nsk 3766,4979 r90 top
C11 "GRM033R60J104KE19D" "c0201 nsk" 3681,5338 r270 top
C12 "GRM033R61A105ME44D" "c0201 nsk" 3868,5606 r0 top
C15 "GRM155R60J226ME11D" c0402-nsk 3882.01,5277.28 r180 top
C16 "GRM155R60J226ME11D" c0402-nsk 3882.01,5310.28 r180 top
C17 "GRM033R61A105ME44D" "c0201 nsk" 3868,5498 r0 top
C18 "GRM155R60J226ME11D" c0402-nsk 3626.36,5800.65 r270 top
C25 "GRM155R60J226ME11D" c0402-nsk 3592.36,5800.65 r270 top
C27 "CL10A226MP8NUNE" C0603-NSK 3491,5381 r0 top
C28 "CL10A226MP8NUNE" C0603-NSK 3491,5429 r0 top
C31 "GRM155R60J226ME11D" c0402-nsk 3844,5809 r180 top
C33 "GRM155R60J226ME11D" c0402-nsk 3761,5809 r0 top
C35 "0201X225M6R3NT" "c0201 nsk" 3902,5637 r90 top
C43 "GRM033R61A105ME44D" "c0201 nsk" 3701.75,5337.72 r270 top
C44 "CL10A226MP8NUNE" C0603-NSK 3491,5604 r0 top
C45 "0201X225M6R3NT" "c0201 nsk" 3557,5672 r270 top
C51 "0201X225M6R3NT" "c0201 nsk" 3868,5343 r0 top
C52 "0201X225M6R3NT" "c0201 nsk" 3868,5366 r0 top
C53 "0201X225M6R3NT" "c0201 nsk" 3868,5410 r0 top
C54 "0201X225M6R3NT" "c0201 nsk" 3868,5432 r0 top
C55 "0201X225M6R3NT" "c0201 nsk" 3868,5388 r0 top
C59 "0201X225M6R3NT" "c0201 nsk" 3868,5454 r0 top
C60 "0201X225M6R3NT" "c0201 nsk" 3867.5,5562 r180 top
C61 "0201X225M6R3NT" "c0201 nsk" 3868,5476 r0 top
C62 "0201X225M6R3NT" "c0201 nsk" 3867.5,5584 r180 top
C63 "0201X225M6R3NT" "c0201 nsk" 3868,5520 r0 top
C64 "0201X225M6R3NT" "c0201 nsk" 3867.5,5628 r180 top
C65 "0201X225M6R3NT" "c0201 nsk" 3868,5541 r0 top
C66 "0201X225M6R3NT" "c0201 nsk" 3867.5,5648 r180 top
C69 "0201X225M6R3NT" "c0201 nsk" 4034,5067 r0 top
C70 "CL05A475KP5NRNC" c0402-nsk 4077.8,5257.59 r225 top
C71 "0201X225M6R3NT" "c0201 nsk" 3957,5067 r180 top
C72 "GRM155R60J226ME11D" c0402-nsk 4254.95,5107.41 r180 top
C73 "0201X225M6R3NT" "c0201 nsk" 3903,5199.5 r90 top
C74 "GRM155R60J226ME11D" c0402-nsk 4254.95,5144.69 r180 top
C80 "GRM155R60J226ME11D" c0402-nsk 4254.95,5186.12 r180 top
C81 "GRM155R60J226ME11D" c0402-nsk 4254.95,5228.95 r180 top
C87 "GRM155R60J226ME11D" c0402-nsk 4104.95,5323.63 r180 top
C88 "GRM033R61A105ME44D" "c0201 nsk" 3903,5138 r270 top
C89 "GRM155R60J226ME11D" c0402-nsk 4104.95,5366.46 r180 top
C95 "GRM033R61A104KE15D" "c0201 nsk" 3616,5336 r90 top
C96 "GRM033R61A104KE15D" "c0201 nsk" 4308,4827 r270 top
C97 "GRM033R61A104KE15D" "c0201 nsk" 4307,5413 r270 top
C98 "0201CG220J500NT" "c0201 nsk" 5347,5409.76 r90 top
C99 "0201CG220J500NT" "c0201 nsk" 5346.35,5466.15 r270 top
C100 "0201CG220J500NT" "c0201 nsk" 5353,5530.76 r90 top
C101 "0201CG220J500NT" "c0201 nsk" 5352.45,5632.82 r270 top
C131 "GRM033R61A104KE15D" "c0201 nsk" 4617,5074 r90 top
C136 "GRM033R61A104KE15D" "c0201 nsk" 4617,5461 r90 top
C139 "GRM033R61A104KE15D" "c0201 nsk" 4617,5506 r270 top
C140 "GRM033R61A104KE15D" "c0201 nsk" 4617,5169 r90 top
C146 "GRM033R61A104KE15D" "c0201 nsk" 4617,5124 r270 top
C147 "0201X225M6R3NT" "c0201 nsk" 4617,5216 r270 top
C148 "GRM033R61A104KE15D" "c0201 nsk" 4617,5261 r270 top
C149 "GRM033R61A104KE15D" "c0201 nsk" 4617,5308 r90 top
C150 "GRM033R61A104KE15D" "c0201 nsk" 4617,5412 r270 top
C157 "GRM033R61A104KE15D" "c0201 nsk" 4617,5028 r270 top
C158 "GRM033R61A104KE15D" "c0201 nsk" 4617,5354 r270 top
C159 "GRM033R61A104KE15D" "c0201 nsk" 4617,5554 r90 top
C160 "GRM033R61A104KE15D" "c0201 nsk" 4617,5600 r270 top
C179 "GRM033R61A104KE15D" "c0201 nsk" 3923.75,5900.75 r270 top
C180 "GRM033R61A104KE15D" "c0201 nsk" 3903.75,5900.75 r270 top
C189 "GRM033R61A104KE15D" "c0201 nsk" 5044,4386 r270 top
C190 "GRM033R61A104KE15D" "c0201 nsk" 5585.6,4446.1 r270 top
C191 "GRM033R61A104KE15D" "c0201 nsk" 5566.6,4446.1 r270 top
C192 "GRM033R61A104KE15D" "c0201 nsk" 5526.6,4446.1 r270 top
C193 "GRM033R61A104KE15D" "c0201 nsk" 5507.6,4446.1 r270 top
C194 "GRM033R61A104KE15D" "c0201 nsk" 5473.6,4446.1 r270 top
C195 "GRM033R61A104KE15D" "c0201 nsk" 5454.6,4446.1 r270 top
C196 "GRM033R61A104KE15D" "c0201 nsk" 5415.6,4446.1 r270 top
C197 "GRM033R61A104KE15D" "c0201 nsk" 5395.6,4446.1 r270 top
C198 "GRM033R61A104KE15D" "c0201 nsk" 5282,4446 r270 top
C199 "GRM033R61A104KE15D" "c0201 nsk" 5303,4446 r270 top
C210 "GRM033R61A104KE15D" "c0201 nsk" 3658,5813 r270 top
C218 "GRM033R61A104KE15D" "c0201 nsk" 3679,5813 r270 top
C219 "GRM033R61A104KE15D" "c0201 nsk" 4515.25,4148.25 r270 top
C220 "GRM033R61A104KE15D" "c0201 nsk" 4494.25,4148.25 r270 top
C221 "CAP_0402" c0402-nsk 4882.95,4411.98 r0 top
C222 "CAP_0402" c0402-nsk 4883,4380 r0 top
C244 "GRM033R61A104KE15D" "c0201 nsk" 3844.57,5997.22 r270 top
C245 "GRM033R61A104KE15D" "c0201 nsk" 3781.57,5997.22 r270 top
C249 "0201X225M6R3NT" "c0201 nsk" 5932,4523 r90 top
C250 "0201X225M6R3NT" "c0201 nsk" 5912,4523 r90 top
C251 "0201CG220J500NT" "c0201 nsk" 5797,4284 r90 top
C252 "0201CG220J500NT" "c0201 nsk" 5797,4340 r270 top
C253 "0201X225M6R3NT" "c0201 nsk" 5774,4484 r270 top
C254 "0201X225M6R3NT" "c0201 nsk" 5774,4531 r90 top
C256 "0201X225M6R3NT" "c0201 nsk" 6645,4517 r90 top
C257 "0201CG220J500NT" "c0201 nsk" 6527,4274 r90 top
C258 "0201X225M6R3NT" "c0201 nsk" 6625,4517 r90 top
C259 "0201CG220J500NT" "c0201 nsk" 6527,4330 r270 top
C260 "0201X225M6R3NT" "c0201 nsk" 6489,4525 r90 top
C261 "0201X225M6R3NT" "c0201 nsk" 6489,4479 r270 top
C262 "0201X225M6R3NT" "c0201 nsk" 5762.5,4199 r180 top
C263 "0201X225M6R3NT" "c0201 nsk" 5729,4439 r90 top
C264 "0201X225M6R3NT" "c0201 nsk" 6150,4265 r0 top
C265 "0201X225M6R3NT" "c0201 nsk" 5763,4246 r180 top
C266 "0201X225M6R3NT" "c0201 nsk" 6010,4185 r270 top
C267 "0201X225M6R3NT" "c0201 nsk" 5930,4185 r270 top
C268 "0201X225M6R3NT" "c0201 nsk" 6095,4524 r270 top
C269 "0201X225M6R3NT" "c0201 nsk" 6491,4198 r180 top
C270 "0201X225M6R3NT" "c0201 nsk" 6863,4256 r0 top
C271 "0201X225M6R3NT" "c0201 nsk" 6464,4416 r90 top
C272 "0201X225M6R3NT" "c0201 nsk" 6725,4184 r270 top
C273 "0201X225M6R3NT" "c0201 nsk" 6491,4240 r180 top
C274 "0201X225M6R3NT" "c0201 nsk" 6797.2,4516.38 r90 top
C275 "0201X225M6R3NT" "c0201 nsk" 6647,4185 r90 top
C280 "CAP_0402" c0402-nsk 7103,6073 r90 top
C281 "CAP_0603" C0603-NSK 6907.77,6056.2 r90 top
C282 "CAP_0603" C0603-NSK 6855.31,6056.2 r90 top
C283 "CL10A226MP8NUNE" C0603-NSK 4005,4980.46 r0 top
C284 "CL10A226MP8NUNE" C0603-NSK 4005,5031.46 r0 top
C290 "CL10A226MP8NUNE" C0603-NSK 3517,5777.46 r0 top
C291 "CL10A226MP8NUNE" C0603-NSK 3517,5728 r0 top
C292 "CL10A226MP8NUNE" C0603-NSK 3776,5767 r0 top
C293 "CL10A226MP8NUNE" C0603-NSK 3859,5737 r270 top
CGQ1 "IRM-H638T/TR2" SENSOR-SMD_IRM-H638T-TR2-TL 7160.88,3997.8 r90 top
CN2 "PJ-327A0-SMT" AUDIO-SMD_PJ-327A0-SMT 6193,6163 r270 top
CN3 "0533980271" CONN-SMD_2P-P1.25_053398-0X71 7148,4347 r90 top
CN4 "0533980271" CONN-SMD_2P-P1.25_053398-0X71 4122,4660 r90 top
D1 "B5819WS_C22624" SOD-323_L1.8-W1.3-LS2.5-RD 4027,4793 r90 top
D2 "SMCJ15CA_C438202" SMC_L6.9-W5.9-LS7.9-BI 3846,4068 r0 top
D3 "SS54_C22452" SMA_L4.4-W2.8-LS5.4-R-RD 3737,5160 r180 top
D4 "SS54_C22452" SMA_L4.4-W2.8-LS5.4-R-RD 3570,4668 r180 top
D5 "RClamp0524PATCT_C40960" SLP2510P8_L2.5-W1.0-P0.50-BL 5216,4282 r180 top
D6 "RClamp0524PATCT_C40960" SLP2510P8_L2.5-W1.0-P0.50-BL 5103,4282 r180 top
D7 "B5819WT_C2997265" "SOD-523_L1.2-W0.8-LS1.6-RD-1 NSK" 4866,4285 r270 top
D8 "RClamp0524PATCT_C40960" SLP2510P8_L2.5-W1.0-P0.50-BL 4990,4282 r0 top
D9 "B5819WT_C2997265" "SOD-523_L1.2-W0.8-LS1.6-RD-1 NSK" 4906,4285 r90 top
D10 "RClamp0524PATCT_C40960" SLP2510P8_L2.5-W1.0-P0.50-BL 5547.15,4382.81 r180 top
D11 "RClamp0524PATCT_C40960" SLP2510P8_L2.5-W1.0-P0.50-BL 5434.73,4383.23 r180 top
D12 "RClamp0524PATCT_C40960" SLP2510P8_L2.5-W1.0-P0.50-BL 5322,4383 r0 top
D13 "RClamp0524PATCT_C40960" SLP2510P8_L2.5-W1.0-P0.50-BL 4649.4,4086.34 r180 top
D14 "RClamp0524PATCT_C40960" SLP2510P8_L2.5-W1.0-P0.50-BL 4328,4087 r180 top
D15 "RClamp0524PATCT_C40960" SLP2510P8_L2.5-W1.0-P0.50-BL 4535,4087 r180 top
D24 "0402ESDA-05N" D0402 6777,6076 r90 top
D25 "0402ESDA-05N" D0402 6743,6076 r90 top
D26 "0402ESDA-05N" D0402 6693,6076 r90 top
D27 "0402ESDA-05N" D0402 6658,6076 r90 top
D30 "0402ESDA-05N" D0402 6812,6076 r90 top
D31 "0402ESDA-05N" D0402 6622,6076 r90 top
DC1 "DC-044A-A200" DC-IN-TH_DC-044A-20A 3843,3723.76 r90 top
FAN "FAN2510" FAN2510 5252,5852 r270 top
FEL1 "YTSA016A0252501B" SW-SMD_4P-L4.2-W3.4-P2.15-LS4.5-TL 4434,4822 r0 top
H1 "12251220ANG0S115001" HDR-TH_40P-P2.54-V-M-R2-C20-S2.54 4609,6293 r0 top
IMPORTED_IMAGE "IMPORTED_IMAGE" IMPORTED_IMAGE 5811,4728 r0 top
IMPORTED_IMAGE "IMPORTED_IMAGE" IMPORTED_IMAGE 4242,4636 r0 top
IMPORTED_IMAGE "IMPORTED_IMAGE" IMPORTED_IMAGE 4509,6094 r0 top
IMPORTED_IMAGE "IMPORTED_IMAGE" IMPORTED_IMAGE 5219,4754 r0 top
IMPORTED_IMAGE "IMPORTED_IMAGE" IMPORTED_IMAGE 4882,6160 r0 top
IMPORTED_IMAGE "IMPORTED_IMAGE" IMPORTED_IMAGE 6930,4861 r0 top
L1 "FXL0630-4R7-M" IND-SMD_L7.0-W6.6 3561.85,4903.18 r90 top
L2 "TFM201610ALM-1R0MTAA" ind-smd_l2.0-w1.6_1 3775,5309 r180 top
L3 "TFM201610ALM-1R0MTAA" ind-smd_l2.0-w1.6_1 3638,5693 r0 top
L4 "TFM201610ALM-1R0MTAA" ind-smd_l2.0-w1.6_1 3766,5693 r180 top
L5 "TFM201610ALM-1R0MTAA" ind-smd_l2.0-w1.6_1 3500,5520 r90 top
L6 "TFM201610ALM-1R0MTAA" ind-smd_l2.0-w1.6_1 4142.84,5103.49 r180 top
L7 "TFM201610ALM-1R0MTAA" ind-smd_l2.0-w1.6_1 4142.84,5201.49 r180 top
L8 "TFM201610ALM-1R0MTAA" ind-smd_l2.0-w1.6_1 4012.84,5319.49 r270 top
L9 "WPN252012H2R2MT" IND-SMD_L2.0-W1.6 5843,4508 r0 top
L10 "WPN252012H2R2MT" IND-SMD_L2.0-W1.6 6558,4502 r0 top
LED1 "LED_0807-RGB" RGBLED_0807 4028.63,5453.84 r0 top
LED2 "WS2812B-2020" LED-SMD_4P-L2.0-W2.0-TL_WS2812B-2020 3487.18,4152.77 r180 top
LED3 "WS2812B-2020" LED-SMD_4P-L2.0-W2.0-TL_WS2812B-2020 3487.18,4036.52 r180 top
LED4 "WS2812B-2020" LED-SMD_4P-L2.0-W2.0-TL_WS2812B-2020 3487.18,3920.26 r180 top
LED5 "WS2812B-2020" LED-SMD_4P-L2.0-W2.0-TL_WS2812B-2020 3487.18,3804 r180 top
PWR1 "YTSA016A0252501B" SW-SMD_4P-L4.2-W3.4-P2.15-LS4.5-TL 4434,5410 r0 top
Q1 "YJL2305A" SOT-23-3_L2.9-W1.3-P1.90-LS2.4-BR 4073,4226 r90 top
R1 "Res_0603" "R0603 NSK" 4066,4337 r180 top
R2 "Res_0603" "R0603 NSK" 4160,4308 r90 top
R3 "Res_0402" R0402-NSK 3908,4979 r90 top
R4 "Res_0402" R0402-NSK 3967.45,4575.76 r0 top
R5 "Res_0402" R0402-NSK 3856.85,4959.18 r0 top
R6 "Res_0402" R0402-NSK 3967.27,4614.78 r180 top
R7 "Res_0402" R0402-NSK 3784,5034 r180 top
R8 "Res_0402" R0402-NSK 3856.85,4998.18 r180 top
R9 "Res_0201" "r0201 nsk" 3595,5339 r90 top
R10 "Res_0201" "r0201 nsk" 3657,5338 r90 top
R11 "Res_0201" "r0201 nsk" 3551.77,5338.77 r90 top
R12 "Res_0201" "r0201 nsk" 3572.77,5338.77 r90 top
R13 "Res_0201" "r0201 nsk" 3514.47,5672 r270 top
R14 "Res_0201" "r0201 nsk" 3536,5672 r270 top
R17 "Res_0201" "r0201 nsk" 3990,5510 r180 top
R19 "Res_0201" "r0201 nsk" 5724.27,5788.27 r90 top
R20 "Res_0201" "r0201 nsk" 5746.27,5788.27 r90 top
R21 "Res_0201" "r0201 nsk" 4268,5001 r270 top
R22 "Res_0201" "r0201 nsk" 4308,4781 r90 top
R23 "Res_0201" "r0201 nsk" 4307.07,5369.69 r90 top
R25 "Res_0201" "r0201 nsk" 5352.45,5580.32 r90 top
R30 "Res_0201" "r0201 nsk" 5658,5788 r90 top
R31 "Res_0201" "r0201 nsk" 5702,5788 r90 top
R32 "Res_0201" "r0201 nsk" 5591,5788 r90 top
R33 "Res_0201" "r0201 nsk" 5636,5788 r270 top
R34 "Res_0201" "r0201 nsk" 5680,5788 r270 top
R35 "Res_0201" "r0201 nsk" 5614,5788 r270 top
R36 "Res_0201" "r0201 nsk" 5064,5162 r90 top
R37 "Res_0201" "r0201 nsk" 5098,5429 r0 top
R41 "Res_0201" "r0201 nsk" 5680.15,4944.85 r0 top
R42 "Res_0201" "r0201 nsk" 6215,5310 r0 top
R43 "Res_0201" "r0201 nsk" 5828,5788 r90 top
R47 "Res_0201" "r0201 nsk" 4866,4217 r90 top
R48 "Res_0201" "r0201 nsk" 4936,4344 r270 top
R50 "Res_0201" "r0201 nsk" 4959,4344 r270 top
R51 "Res_0201" "r0201 nsk" 5002,4344 r270 top
R52 "Res_0201" "r0201 nsk" 4981,4344 r270 top
R53 "Res_0201" "r0201 nsk" 5023,4344 r270 top
R54 "Res_0201" "r0201 nsk" 5044,4344 r270 top
R60 "Res_0201" "r0201 nsk" 5361,4446 r90 top
R61 "Res_0201" "r0201 nsk" 5323,4446 r270 top
R62 "Res_0201" "r0201 nsk" 5260,4446 r270 top
R69 "Res_0201" "r0201 nsk" 3912.28,5841.7 r0 top
R70 "Res_0201" "r0201 nsk" 3912,5817 r0 top
R72 "Res_0201" "r0201 nsk" 3812.57,5986.22 r180 top
R77 "Res_0201" "r0201 nsk" 7047.19,4265.26 r90 top
R78 "Res_0201" "r0201 nsk" 7067.26,4265.34 r90 top
R79 "Res_0201" "r0201 nsk" 5608,3682 r270 top
R80 "Res_0201" "r0201 nsk" 5631,3682 r90 top
R82 "Res_0201" "r0201 nsk" 6047,4523 r270 top
R83 "Res_0201" "r0201 nsk" 6150,4320 r180 top
R85 "Res_0201" "r0201 nsk" 5763,4223 r0 top
R86 "Res_0201" "r0201 nsk" 6023.47,4523 r270 top
R88 "Res_0201" "r0201 nsk" 5762,4449 r0 top
R89 "Res_0201" "r0201 nsk" 5999,4523 r90 top
R90 "Res_0201" "r0201 nsk" 6150,4288 r180 top
R91 "Res_0201" "r0201 nsk" 6072,4523 r90 top
R92 "Res_0201" "r0201 nsk" 5762,4427 r180 top
R93 "Res_0201" "r0201 nsk" 5954,4523 r270 top
R94 "Res_0201" "r0201 nsk" 5631,3725 r270 top
R95 "Res_0201" "r0201 nsk" 5976,4523 r270 top
R96 "Res_0201" "r0201 nsk" 5608,3725 r270 top
R97 "Res_0201" "r0201 nsk" 6338.37,3678.12 r270 top
R98 "Res_0201" "r0201 nsk" 6362.37,3678.12 r90 top
R100 "Res_0201" "r0201 nsk" 6754,4517 r270 top
R101 "Res_0201" "r0201 nsk" 6863,4314 r180 top
R103 "Res_0201" "r0201 nsk" 6491,4219 r0 top
R104 "Res_0201" "r0201 nsk" 6732,4517 r270 top
R106 "Res_0201" "r0201 nsk" 6494,4426 r0 top
R107 "Res_0201" "r0201 nsk" 6709,4517 r90 top
R108 "Res_0201" "r0201 nsk" 6863,4280.53 r180 top
R109 "Res_0201" "r0201 nsk" 6776,4517 r90 top
R110 "Res_0201" "r0201 nsk" 6494,4405 r180 top
R111 "Res_0201" "r0201 nsk" 6666,4517 r270 top
R112 "Res_0201" "r0201 nsk" 6362.37,3719.12 r270 top
R113 "Res_0201" "r0201 nsk" 6687,4517 r270 top
R114 "Res_0201" "r0201 nsk" 6338.37,3719.12 r270 top
R117 "Res_0201" "r0201 nsk" 6962.77,5975.66 r0 top
R118 "Res_0201" "r0201 nsk" 7067.77,5975.2 r0 top
R120 "Res_0201" "r0201 nsk" 6973.23,6155.23 r270 top
R121 "Res_0201" "r0201 nsk" 6994,6155 r90 top
R123 "Res_0201" "r0201 nsk" 5920,5793 r270 top
R124 "Res_0201" "r0201 nsk" 7052.62,4125.46 r90 top
R125 "Res_0201" "r0201 nsk" 7073.62,4125.46 r90 top
R129 "Res_0201" "r0201 nsk" 6594,6085 r90 top
R130 "Res_0201" "r0201 nsk" 6782,6020 r180 top
RESET1 "YTSA016A0252501B" SW-SMD_4P-L4.2-W3.4-P2.15-LS4.5-TL 4434,5116 r0 top
RF1 "BWIPX-1-001E" IPEX-SMD_BWIPX-1-001E 3708,5986 r180 top
RJ1 "HR911130A" RJ45-TH_HR911130A 5993,3791.76 r180 top
RJ2 "HR911130A" RJ45-TH_HR911130A 6712,3791 r180 top
TFT1 "1.14 IPS DISPLAY ST7789V" TFT_1.14寸_0.7MM-13P 6923,5232 r270 top
U1 "RVT1H101M0607" CAP-SMD_BD6.3-L6.6-W6.6-LS7.6-RD 3567.64,4414.49 r90 top
U2 "RVT1H101M0607" CAP-SMD_BD6.3-L6.6-W6.6-LS7.6-RD 3860.52,4414.64 r90 top
U3 "TPS54531DDAR" SOIC-8_L5.0-W4.0-P1.27-LS6.0-BL-EP2.0 3845,4780 r0 top
U4 "AXP717B" QFN-52_L6.0-W6.0-P0.40-BL-EP3.4-1 3689.11,5500.48 r0 top
U5 "AXP323" QFN-20_L3.0-W3.0-P0.40-BL-EP1.5 3987.84,5153.49 r180 top
U8 "EMMC BGA153" FBGA-153_L13.0-W11.5 4900,4745 r270 top
U9 "XR829MQ" LGA-44_L12.0-W12.0-P0.90 4196,5843 r0 top
U12 "RTL8211F-CG" WQFN-40_L5.0-W5.0-P0.4-BL-EP 5970,4343 r0 top
U13 "RTL8211F-CG" WQFN-40_L5.0-W5.0-P0.4-BL-EP 6684.91,4337.51 r0 top
U14 "T527" T527-BGA664 5766.98,5355.47 r270 top
U15 "DP_TH_SIDE_VERTICAL" DP_TH_SIDE_VERTICAL 5439,3797 r180 top
U17 "SY6280AAC_C55136" SOT-23-5_L3.0-W1.7-P0.95-LS2.8-BL 7014.46,6055.02 r270 top
UD1 "LPDDR4_FBGA200" BGA200P65_80B1000_1500H90 4836.54,5314.87 r180 top
USB1 "HDMI-001C_C2836126" HDMI-SMD_HDMI-001C 5042.58,3905.2 r270 top
USB2 "USB-303WSD-BRY" USB-A-TH_XUNPU_USB-303WSD-BRY 4491,3798 r0 top
USB3 "TYPEC-304-BCP16" USB-C-SMD_TYPEC-304-BCP16-1 6720,6259 r180 top
X1 "TAXM24M4ZDBCCT2T" crystal-smd_4p-l2.0-w1.6-bl-nsk 5298,5438.46 r270 top
X2 "Q13FC1350000400" "osc-smd_l3.2-w1.5 nsk" 5298.45,5582.32 r90 top
X3 "7D025000Q01" crystal-smd_4p-l2.0-w1.6-bl-nsk 5749,4314 r270 top
X4 "7D025000Q01" crystal-smd_4p-l2.0-w1.6-bl-nsk 6478,4302 r270 top

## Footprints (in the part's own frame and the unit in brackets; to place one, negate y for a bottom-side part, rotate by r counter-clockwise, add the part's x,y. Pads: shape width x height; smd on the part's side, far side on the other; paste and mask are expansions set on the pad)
AUDIO-SMD_PJ-327A0-SMT [mm]
  rect 1.8x3 smd: 2(3.15,-4.028) 3(-3.75,-4.028) 4(-4.75,4.028) 5(-1.15,4.028) 6(4.75,4.028)
  Board Outline Layer lines w0.254: -6.24,-2.54 -6.24,2.56 ; -6.24,-2.54 -8.34,-2.54 -6.24,-2.54 ; -6.24,-2.54 -6.24,2.56 ; -6.24,2.56 -6.4,2.56 ; -6.24,2.56 -6.4,2.56 ; -6.4,2.56 -8.44,2.56 -6.4,2.56
  Multi-Layer board cut-out: -3.35,0.5 -3.622,0.424 -3.82,0.223 -3.892,-0.05 -3.82,-0.323 -3.622,-0.524 -3.35,-0.6 -3.35,-0.6 -3.078,-0.524 -2.88,-0.323 -2.807,-0.05 -2.88,0.223 -3.078,0.424 -3.35,0.5
  Multi-Layer board cut-out: 2.65,0.5 2.378,0.424 2.18,0.223 2.108,-0.05 2.18,-0.323 2.378,-0.524 2.65,-0.6 2.65,-0.6 2.922,-0.524 3.12,-0.323 3.193,-0.05 3.12,0.223 2.922,0.424 2.65,0.5
  Multi-Layer keep-out circle w0.254: c-3.35,-0.05 r0.55
  Multi-Layer keep-out circle w0.254: c2.65,-0.05 r0.55
  silkscreen extent -8.43,-3.23 5.6,3.17
BGA200P65_80B1000_1500H90 [mm]
  round 0.27 smd: A1(-4.4,6.825) A2(-3.6,6.825) A3(-2.8,6.825) A4(-2,6.825) A5(-1.2,6.825) A8(1.2,6.825) A9(2,6.825) A10(2.8,6.825) A11(3.6,6.825) A12(4.4,6.825) AA1(-4.4,-6.175) AA2(-3.6,-6.175) AA3(-2.8,-6.175) AA4(-2,-6.175) AA5(-1.2,-6.175) AA8(1.2,-6.175) AA9(2,-6.175) AA10(2.8,-6.175) AA11(3.6,-6.175) AA12(4.4,-6.175) AB1(-4.4,-6.825) AB2(-3.6,-6.825) AB3(-2.8,-6.825) AB4(-2,-6.825) AB5(-1.2,-6.825) AB8(1.2,-6.825) AB9(2,-6.825) AB10(2.8,-6.825) AB11(3.6,-6.825) AB12(4.4,-6.825) B1(-4.4,6.175) B2(-3.6,6.175) B3(-2.8,6.175) B4(-2,6.175) B5(-1.2,6.175) B8(1.2,6.175) B9(2,6.175) B10(2.8,6.175) B11(3.6,6.175) B12(4.4,6.175) C1(-4.4,5.525) C2(-3.6,5.525) C3(-2.8,5.525) C4(-2,5.525) C5(-1.2,5.525) C8(1.2,5.525) C9(2,5.525) C10(2.8,5.525) C11(3.6,5.525) C12(4.4,5.525) D1(-4.4,4.875) D2(-3.6,4.875) D3(-2.8,4.875) D4(-2,4.875) D5(-1.2,4.875) D8(1.2,4.875) D9(2,4.875) D10(2.8,4.875) D11(3.6,4.875) D12(4.4,4.875) E1(-4.4,4.225) E2(-3.6,4.225) E3(-2.8,4.225) E4(-2,4.225) E5(-1.2,4.225) E8(1.2,4.225) E9(2,4.225) E10(2.8,4.225) E11(3.6,4.225) E12(4.4,4.225) F1(-4.4,3.575) F2(-3.6,3.575) F3(-2.8,3.575) F4(-2,3.575) F5(-1.2,3.575) F8(1.2,3.575) F9(2,3.575) F10(2.8,3.575) F11(3.6,3.575) F12(4.4,3.575) G1(-4.4,2.925) G2(-3.6,2.925) G3(-2.8,2.925) G4(-2,2.925) G5(-1.2,2.925) G8(1.2,2.925) G9(2,2.925) G10(2.8,2.925) G11(3.6,2.925) G12(4.4,2.925) H1(-4.4,2.275) H2(-3.6,2.275) H3(-2.8,2.275) H4(-2,2.275) H5(-1.2,2.275) H8(1.2,2.275) H9(2,2.275) H10(2.8,2.275) H11(3.6,2.275) H12(4.4,2.275) J1(-4.4,1.625) J2(-3.6,1.625) J3(-2.8,1.625) J4(-2,1.625) J5(-1.2,1.625) J8(1.2,1.625) J9(2,1.625) J10(2.8,1.625) J11(3.6,1.625) J12(4.4,1.625) K1(-4.4,0.975) K2(-3.6,0.975) K3(-2.8,0.975) K4(-2,0.975) K5(-1.2,0.975) K8(1.2,0.975) K9(2,0.975) K10(2.8,0.975) K11(3.6,0.975) K12(4.4,0.975) N1(-4.4,-0.975) N2(-3.6,-0.975) N3(-2.8,-0.975) N4(-2,-0.975) N5(-1.2,-0.975) N8(1.2,-0.975) N9(2,-0.975) N10(2.8,-0.975) N11(3.6,-0.975) N12(4.4,-0.975) P1(-4.4,-1.625) P2(-3.6,-1.625) P3(-2.8,-1.625) P4(-2,-1.625) P5(-1.2,-1.625) P8(1.2,-1.625) P9(2,-1.625) P10(2.8,-1.625) P11(3.6,-1.625) P12(4.4,-1.625) R1(-4.4,-2.275) R2(-3.6,-2.275) R3(-2.8,-2.275) R4(-2,-2.275) R5(-1.2,-2.275) R8(1.2,-2.275) R9(2,-2.275) R10(2.8,-2.275) R11(3.6,-2.275) R12(4.4,-2.275) T1(-4.4,-2.925) T2(-3.6,-2.925) T3(-2.8,-2.925) T4(-2,-2.925) T5(-1.2,-2.925) T8(1.2,-2.925) T9(2,-2.925) T10(2.8,-2.925) T11(3.6,-2.925) T12(4.4,-2.925) U1(-4.4,-3.575) U2(-3.6,-3.575) U3(-2.8,-3.575) U4(-2,-3.575) U5(-1.2,-3.575) U8(1.2,-3.575) U9(2,-3.575) U10(2.8,-3.575) U11(3.6,-3.575) U12(4.4,-3.575) V1(-4.4,-4.225) V2(-3.6,-4.225) V3(-2.8,-4.225) V4(-2,-4.225) V5(-1.2,-4.225) V8(1.2,-4.225) V9(2,-4.225) V10(2.8,-4.225) V11(3.6,-4.225) V12(4.4,-4.225) W1(-4.4,-4.875) W2(-3.6,-4.875) W3(-2.8,-4.875) W4(-2,-4.875) W5(-1.2,-4.875) W8(1.2,-4.875) W9(2,-4.875) W10(2.8,-4.875) W11(3.6,-4.875) W12(4.4,-4.875) Y1(-4.4,-5.525) Y2(-3.6,-5.525) Y3(-2.8,-5.525) Y4(-2,-5.525) Y5(-1.2,-5.525) Y8(1.2,-5.525) Y9(2,-5.525) Y10(2.8,-5.525) Y11(3.6,-5.525) Y12(4.4,-5.525)
  silkscreen extent -5.75,-7.55 5.05,7.55
"c0201 nsk" [mil]
  rect 14.51x12.76 smd: 1(-11.5,0) 2(11,0)
c0402-nsk [mil]
  rect 22x22 smd: 1(-19.99,0) 2(20.01,0)
  silkscreen extent 0,-5 0,6
C0603-NSK [mm]
  rect 0.85x0.85 smd: 1(-0.75,0) 2(0.75,0)
  silkscreen extent 0,-0.21 0,0.21
"C0805 NSK" [mm]
  rect 1.3x1.35 smd: 1(-1.03,0) 2(1.03,0)
  silkscreen extent 0,-0.44 0,0.44
CAP-SMD_BD6.3-L6.6-W6.6-LS7.6-RD [mm]
  rect 3.5x1.2 smd: 1(-2.67,0) 2(2.67,0)
  silkscreen extent -3.38,-3.38 3.38,3.38
CONN-SMD_2P-P1.25_053398-0X71 [mm]
  rect 0.8x1.6 smd: 1(-0.63,1.45) 2(0.63,1.45)
  rect 2x3 smd: 3(3.23,-1.45) 4(-3.23,-1.45)
  silkscreen extent -3.68,-2.6 3.68,1.21
crystal-smd_4p-l2.0-w1.6-bl-nsk [mil]
  rect 33.3x21.5 smd: 1(-30,-20) 2(30,-20) 3(30,20) 4(-30,20)
D0402 [mil]
  rect 19.89x21.68 smd: 1(-16.4,0) 2(16.4,0)
  silkscreen extent -37,-9 -31,9
DC-IN-TH_DC-044A-20A [mm]
  oval 3x1.6 hole 1 slot 2.2 at 0 deg: 1(3.625,-4.5) 2(3.625,4.001) 3(3.625,-1.3) 4(-3.625,-4.9) 5(-3.625,4.9)
  Multi-Layer board cut-out: -2.6,-2.3 -2.079,-2.156 -1.699,-1.772 -1.56,-1.25 -1.699,-0.728 -2.079,-0.344 -2.6,-0.2 -2.6,-0.2 -3.121,-0.344 -3.501,-0.728 -3.64,-1.25 -3.501,-1.772 -3.121,-2.156 -2.6,-2.3
  Multi-Layer keep-out circle w0.254: c-2.6,-1.25 r1.05
  silkscreen extent -6.7,-5.1 4.95,5
DP_TH_SIDE_VERTICAL [mil]
  round 35 hole 25: 1(-30.5,34.6) 2(28.5,60.2) 3(-30.5,-16.6) 4(28.5,9) 5(-30.5,-67.7) 6(28.5,-42.2) 7(-30.5,-118.9) 8(28.5,-93.3) 9(-30.5,-170.1) 10(28.5,-144.5) 11(-30.5,-221.3) 12(28.5,-195.7) 13(-30.5,-272.5) 14(28.5,-246.9) 15(-30.5,-323.7) 16(28.5,-298.1) 17(-30.5,-374.8) 18(28.5,-349.2) 19(-30.5,-426) 20(28.5,-400.4)
  oval 47.2x94.5 hole 39.37 slot 78.74 at 90 deg: 21(98.6,100.8) 22(98.6,-354) 23(-100.6,-436.6) 24(-100.6,27.9)
  Multi-Layer board cut-out: 32,-446 34.97,-459.02 43.3,-469.45 55.32,-475.25 68.68,-475.25 80.7,-469.45 89.03,-459.02 92,-446 92,-446 89.03,-432.98 80.7,-422.55 68.68,-416.75 55.32,-416.75 43.3,-422.55 34.97,-432.98 32,-446
  Multi-Layer board cut-out: -94,105.5 -91.03,92.48 -82.7,82.05 -70.68,76.25 -57.32,76.25 -45.3,82.05 -36.97,92.48 -34,105.5 -34,105.5 -36.97,118.52 -45.3,128.95 -57.32,134.75 -70.68,134.75 -82.7,128.95 -91.03,118.52 -94,105.5
  Multi-Layer keep-out circle w10: c62,-446 r30
  Multi-Layer keep-out circle w10: c-64,105.5 r30
  silkscreen extent -119,-513 117,511
FAN2510 [mm]
  round 3.5 hole 2.7: 1(28.321,23.114) 2(-2.54,2.921)
FBGA-153_L13.0-W11.5 [mm]
  oval 0.2x0.305 smd: A1(-3.25,3.25) A2(-2.75,3.25) A3(-2.25,3.25) A4(-1.75,3.25) A5(-1.25,3.25) A6(-0.75,3.25) A7(-0.25,3.25) A8(0.25,3.25) A9(0.75,3.25) A10(1.25,3.25) A11(1.75,3.25) A12(2.25,3.25) A13(2.75,3.25) A14(3.25,3.25) P1(-3.25,-3.25) P2(-2.75,-3.25) P3(-2.25,-3.25) P4(-1.75,-3.25) P5(-1.25,-3.25) P6(-0.75,-3.25) P7(-0.25,-3.25) P8(0.25,-3.25) P9(0.75,-3.25) P10(1.25,-3.25) P11(1.75,-3.25) P12(2.25,-3.25) P13(2.75,-3.25) P14(3.25,-3.25)
  oval 0.305x0.2 smd: B1(-3.25,2.75) B14(3.25,2.75) C1(-3.25,2.25) C14(3.25,2.25) D1(-3.25,1.75) D14(3.25,1.75) E1(-3.25,1.25) E14(3.25,1.25) F1(-3.25,0.75) F14(3.25,0.75) G1(-3.25,0.25) G14(3.25,0.25) H1(-3.25,-0.25) H14(3.25,-0.25) J1(-3.25,-0.75) J14(3.25,-0.75) K1(-3.25,-1.25) K14(3.25,-1.25) L1(-3.25,-1.75) L14(3.25,-1.75) M1(-3.25,-2.25) M14(3.25,-2.25) N1(-3.25,-2.75) N14(3.25,-2.75)
  round 0.25 smd: B2(-2.75,2.75) B3(-2.25,2.75) B4(-1.75,2.75) B5(-1.25,2.75) B6(-0.75,2.75) B7(-0.25,2.75) B8(0.25,2.75) B9(0.75,2.75) B10(1.25,2.75) B11(1.75,2.75) B12(2.25,2.75) B13(2.75,2.75) C2(-2.75,2.25) C3(-2.25,2.25) C4(-1.75,2.25) C5(-1.25,2.25) C6(-0.75,2.25) C7(-0.25,2.25) C8(0.25,2.25) C9(0.75,2.25) C10(1.25,2.25) C11(1.75,2.25) C12(2.25,2.25) C13(2.75,2.25) D2(-2.75,1.75) D3(-2.25,1.75) D4(-1.75,1.75) D12(2.25,1.75) D13(2.75,1.75) E2(-2.75,1.25) E3(-2.25,1.25) E5(-1.25,1.25) E6(-0.75,1.25) E7(-0.25,1.25) E8(0.25,1.25) E9(0.75,1.25) E10(1.25,1.25) E12(2.25,1.25) E13(2.75,1.25) F2(-2.75,0.75) F3(-2.25,0.75) F5(-1.25,0.75) F10(1.25,0.75) F12(2.25,0.75) F13(2.75,0.75) G2(-2.75,0.25) G3(-2.25,0.25) G5(-1.25,0.25) G10(1.25,0.25) G12(2.25,0.25) G13(2.75,0.25) H2(-2.75,-0.25) H3(-2.25,-0.25) H5(-1.25,-0.25) H10(1.25,-0.25) H12(2.25,-0.25) H13(2.75,-0.25) J2(-2.75,-0.75) J3(-2.25,-0.75) J5(-1.25,-0.75) J10(1.25,-0.75) J12(2.25,-0.75) J13(2.75,-0.75) K2(-2.75,-1.25) K3(-2.25,-1.25) K5(-1.25,-1.25) K6(-0.75,-1.25) K7(-0.25,-1.25) K8(0.25,-1.25) K9(0.75,-1.25) K10(1.25,-1.25) K12(2.25,-1.25) K13(2.75,-1.25) L2(-2.75,-1.75) L3(-2.25,-1.75) L12(2.25,-1.75) L13(2.75,-1.75) M2(-2.75,-2.25) M3(-2.25,-2.25) M4(-1.75,-2.25) M5(-1.25,-2.25) M6(-0.75,-2.25) M7(-0.25,-2.25) M8(0.25,-2.25) M9(0.75,-2.25) M10(1.25,-2.25) M11(1.75,-2.25) M12(2.25,-2.25) M13(2.75,-2.25) N2(-2.75,-2.75) N3(-2.25,-2.75) N4(-1.75,-2.75) N5(-1.25,-2.75) N6(-0.75,-2.75) N7(-0.25,-2.75) N8(0.25,-2.75) N9(0.75,-2.75) N10(1.25,-2.75) N11(1.75,-2.75) N12(2.25,-2.75) N13(2.75,-2.75)
  silkscreen extent -5.84,-6.61 5.84,6.6
HDMI-SMD_HDMI-001C [mm]
  round 0.8 hole 0.55: 1(5.3,0.5) 2(4.731,-0.5) 3(4.145,0.5) 4(3.575,-0.5) 5(2.99,0.5) 6(2.419,-0.5) 7(1.835,0.5) 8(1.263,-0.5) 9(0.68,0.5) 10(0.107,-0.5) 11(-0.475,0.5) 12(-1.049,-0.5) 13(-1.63,0.5) 14(-2.205,-0.5) 15(-2.785,0.5) 16(-3.361,-0.5) 17(-3.94,0.5) 18(-4.517,-0.5) 19(-5.095,0.5)
  oval 3.2x1.4 hole 0.9 slot 2.7 at 0 deg: 20(-6.05,3.25) 20(-2.95,-3.25) 20(3.45,3.25) 20(6.05,-3.25)
  Multi-Layer board cut-out: 7.2,2.516 6.759,2.415 6.406,2.133 6.209,1.726 6.209,1.274 6.406,0.867 6.759,0.585 7.2,0.484 7.2,0.484 7.708,0.62 8.08,0.992 8.216,1.5 8.08,2.008 7.708,2.38 7.2,2.516
  Multi-Layer board cut-out: -6.05,-0.984 -6.491,-1.085 -6.844,-1.367 -7.04,-1.774 -7.04,-2.226 -6.844,-2.634 -6.491,-2.916 -6.05,-3.016 -6.05,-3.016 -5.542,-2.88 -5.17,-2.508 -5.034,-2 -5.17,-1.492 -5.542,-1.12 -6.05,-0.984
  Multi-Layer keep-out circle w0.254: c7.2,1.5 r1.016
  Multi-Layer keep-out circle w0.254: c-6.05,-2 r1.016
  silkscreen extent -7.4,-3.85 15.7,3.25
HDR-TH_40P-P2.54-V-M-R2-C20-S2.54 [mm]
  rect 1.575x1.8 hole 1.1: 1(-24.13,-1.27)
  round 1.8 hole 1.1: 2(-24.13,1.27) 3(-21.59,-1.27) 4(-21.59,1.27) 5(-19.05,-1.27) 6(-19.05,1.27) 7(-16.51,-1.27) 8(-16.51,1.27) 9(-13.97,-1.27) 10(-13.97,1.27) 11(-11.43,-1.27) 12(-11.43,1.27) 13(-8.89,-1.27) 14(-8.89,1.27) 15(-6.35,-1.27) 16(-6.35,1.27) 17(-3.81,-1.27) 18(-3.81,1.27) 19(-1.27,-1.27) 20(-1.27,1.27) 21(1.27,-1.27) 22(1.27,1.27) 23(3.81,-1.27) 24(3.81,1.27) 25(6.35,-1.27) 26(6.35,1.27) 27(8.89,-1.27) 28(8.89,1.27) 29(11.43,-1.27) 30(11.43,1.27) 31(13.97,-1.27) 32(13.97,1.27) 33(16.51,-1.27) 34(16.51,1.27) 35(19.05,-1.27) 36(19.05,1.27) 37(21.59,-1.27) 38(21.59,1.27) 39(24.13,-1.27) 40(24.13,1.27)
  silkscreen extent -25.4,-2.54 25.4,2.54
IMPORTED_IMAGE [mil]
IND-SMD_L2.0-W1.6 [mm]
  rect 1x1.72 smd: 1(0.828,0) 2(-0.828,0)
  silkscreen extent -1.14,-1.02 1.14,1.02
ind-smd_l2.0-w1.6_1 [mil]
  rect 46x77 smd: 1(35,0) 2(-35,0)
  silkscreen extent -45,-45 45,45
IND-SMD_L7.0-W6.6 [mm]
  rect 2.4x3.2 smd: 1(-3,0) 2(3,0)
  silkscreen extent -3.5,-3.3 3.5,3.3
IPEX-SMD_BWIPX-1-001E [mm]
  rect 1.05x1 smd: 1(-0.763,0)
  rect 2.2x1.05 smd: 2(0.763,-1.475) 3(0.763,1.475)
  silkscreen extent -0.64,-1.27 2.16,1.27
LED-SMD_4P-L2.0-W2.0-TL_WS2812B-2020 [mm]
  rect 0.9x0.7 smd: 1(-0.915,0.55) 2(-0.915,-0.55) 3(0.915,-0.55) 4(0.915,0.55)
  silkscreen extent -1.3,-1.1 1,1.15
LGA-44_L12.0-W12.0-P0.90 [mm]
  rect 1.177x0.6 smd: 1(-5.844,4.5) 2(-5.844,3.6) 3(-5.844,2.7) 4(-5.844,1.8) 5(-5.844,0.9) 6(-5.844,0) 7(-5.844,-0.9) 8(-5.844,-1.8) 9(-5.844,-2.7) 10(-5.844,-3.6) 11(-5.844,-4.5) 23(5.844,-4.5) 24(5.844,-3.6) 25(5.844,-2.7) 26(5.844,-1.8) 27(5.844,-0.9) 28(5.844,0) 29(5.844,0.9) 30(5.844,1.8) 31(5.844,2.7) 32(5.844,3.6) 33(5.844,4.5)
  rect 0.6x1.177 smd: 12(-4.5,-5.844) 13(-3.6,-5.844) 14(-2.7,-5.844) 15(-1.8,-5.844) 16(-0.9,-5.844) 17(0,-5.844) 18(0.9,-5.844) 19(1.8,-5.844) 20(2.7,-5.844) 21(3.6,-5.844) 22(4.5,-5.844) 34(4.5,5.844) 35(3.6,5.844) 36(2.7,5.844) 37(1.8,5.844) 38(0.9,5.844) 39(0,5.844) 40(-0.9,5.844) 41(-1.8,5.844) 42(-2.7,5.844) 43(-3.6,5.844) 44(-4.5,5.844)
  silkscreen extent -7.47,-6.08 6.08,6.08
"osc-smd_l3.2-w1.5 nsk" [mm]
  rect 1.05x1.7 smd: 1(-1.275,0) 2(1.275,0)
QFN-20_L3.0-W3.0-P0.40-BL-EP1.5 [mm]
  rect 0.2x0.665 smd: 1(-0.8,-1.407) 2(-0.4,-1.407) 3(0,-1.407) 4(0.4,-1.407) 5(0.8,-1.407) 11(0.8,1.407) 12(0.4,1.407) 13(0,1.407) 14(-0.4,1.407) 15(-0.8,1.407)
  rect 0.665x0.2 smd: 6(1.407,-0.8) 7(1.407,-0.4) 8(1.407,0) 9(1.407,0.4) 10(1.407,0.8) 16(-1.407,0.8) 17(-1.407,0.4) 18(-1.407,0) 19(-1.407,-0.4) 20(-1.407,-0.8)
  rect 1.5x1.5 smd: 21(0,0)
  silkscreen extent -1.58,-2.01 1.58,1.58
QFN-52_L6.0-W6.0-P0.40-BL-EP3.4-1 [mm]
  oval 0.12x0.351 smd: 1(-2.4,-2.918) 13(2.4,-2.918) 27(2.4,2.917) 39(-2.4,2.917)
  rect 0.2x0.585 smd: 2(-2,-2.918) 3(-1.6,-2.918) 4(-1.2,-2.918) 5(-0.8,-2.918) 6(-0.4,-2.918) 7(0,-2.918) 8(0.4,-2.918) 9(0.8,-2.918) 10(1.2,-2.918) 11(1.6,-2.918) 12(2,-2.918) 28(2,2.917) 29(1.6,2.917) 30(1.2,2.917) 31(0.8,2.917) 32(0.4,2.917) 33(0,2.917) 34(-0.4,2.917) 35(-0.8,2.917) 36(-1.2,2.917) 37(-1.6,2.917) 38(-2,2.917)
  oval 0.351x0.12 smd: 14(2.917,-2.4) 26(2.918,2.4) 40(-2.917,2.4) 52(-2.917,-2.4)
  rect 0.585x0.2 smd: 15(2.917,-2) 16(2.917,-1.6) 17(2.917,-1.2) 18(2.917,-0.8) 19(2.917,-0.4) 20(2.917,0) 21(2.917,0.4) 22(2.917,0.8) 23(2.917,1.2) 24(2.917,1.6) 25(2.917,2) 41(-2.918,2) 42(-2.918,1.6) 43(-2.918,1.2) 44(-2.918,0.8) 45(-2.918,0.4) 46(-2.918,0) 47(-2.918,-0.4) 48(-2.918,-0.8) 49(-2.918,-1.2) 50(-2.918,-1.6) 51(-2.918,-2)
  rect 3.4x3.4 smd: 53(0,0)
  Top Layer region: -2.817,2.5 -2.625,2.4 -2.625,2.3 -3.21,2.3 -3.21,2.5
  Top Layer region: -2.5,2.817 -2.4,2.625 -2.3,2.625 -2.3,3.21 -2.5,3.21
  Top Layer region: 2.5,2.818 2.4,2.625 2.3,2.625 2.3,3.21 2.5,3.21
  Top Layer region: 2.817,2.5 2.625,2.4 2.625,2.3 3.21,2.3 3.21,2.5
  Top Layer region: 2.817,-2.5 2.625,-2.4 2.625,-2.3 3.21,-2.3 3.21,-2.5
  Top Layer region: 2.5,-2.817 2.4,-2.625 2.3,-2.625 2.3,-3.21 2.5,-3.21
  Top Layer region: -2.817,-2.5 -2.625,-2.4 -2.625,-2.3 -3.21,-2.3 -3.21,-2.5
  Top Layer region: -2.5,-2.817 -2.4,-2.625 -2.3,-2.625 -2.3,-3.21 -2.5,-3.21
  silkscreen extent -3.08,-3.53 3.08,3.08
"r0201 nsk" [mil]
  rect 11.93x12.76 smd: 1(-9.51,0) 2(9.51,0)
R0402-NSK [mil]
  rect 19.68x22 smd: 1(-18,0) 2(18,0)
"R0603 NSK" [mil]
  rect 31.75x34.02 smd: 1(-29.66,0) 2(29.66,0)
RGBLED_0807 [mil]
  rect 35.83x70 smd: 1(-36,0) 2(37,0)
  silkscreen extent -6,-33 12,32
RJ45-TH_HR911130A [mil]
  round 66.9 hole 43.3: 11(260,272.6) 12(160,272.6) 13(-160,272.6) 14(-260,272.6)
  rect 60x60 hole 35.8: P1(229.6,-272.6)
  round 60 hole 35.8: P2(179.1,-172.4) P3(125.2,-272.4) P4(79.1,-172.4) P5(25.2,-272.4) P6(-20.9,-172.4) P7(-74.8,-272.4) P8(-120.9,-172.4) P9(-174.8,-272.4) P10(-220.9,-172.4)
  round 85 hole 65: SHIELD0(-315,-42.5) SHIELD1(315,-42.5)
  Multi-Layer board cut-out: -288.4,77.6 -282.06,49.83 -264.3,27.56 -238.64,15.2 -210.16,15.2 -184.5,27.56 -166.74,49.83 -160.4,77.6 -160.4,77.6 -166.74,105.36 -184.5,127.63 -210.16,139.99 -238.64,139.99 -264.3,127.64 -282.06,105.37 -288.4,77.6
  Multi-Layer board cut-out: 160.4,77.6 166.74,49.83 184.5,27.56 210.16,15.2 238.64,15.2 264.3,27.56 282.06,49.83 288.4,77.6 288.4,77.6 282.06,105.36 264.3,127.63 238.64,139.99 210.16,139.99 184.5,127.64 166.74,105.37 160.4,77.6
  Multi-Layer keep-out circle w10: c-224.4,77.6 r64
  Multi-Layer keep-out circle w10: c224.4,77.6 r64
  silkscreen extent -315,-347 315,503
SENSOR-SMD_IRM-H638T-TR2-TL [mm]
  rect 1.5x0.9 smd: 1(-2.95,1.27) 2(-2.95,-1.27) 3(2.95,-1.27) 4(2.921,1.27)
  silkscreen extent -2.99,-2.5 2,2.67
SLP2510P8_L2.5-W1.0-P0.50-BL [mm]
  rect 0.2x0.68 smd: 1(-1,-0.44) 2(-0.5,-0.44) 4(0.5,-0.44) 5(1,-0.44) 6(1,0.44) 7(0.5,0.44) 9(-0.5,0.44) 10(-1,0.44)
  rect 0.4x0.68 smd: 3(0,-0.44) 8(0,0.44)
  silkscreen extent -1.44,-0.88 1.3,0.55
SMA_L4.4-W2.8-LS5.4-R-RD [mil]
  rect 81.2x60.59 smd: 1(98.57,0) 2(-98.57,0)
  silkscreen extent -119,-56 104,56
SMC_L6.9-W5.9-LS7.9-BI [mm]
  rect 3.03x3.82 smd: 1(-3.435,0) 2(3.435,0)
  silkscreen extent -3.6,-3.11 3.6,3.11
SOD-323_L1.8-W1.3-LS2.5-RD [mm]
  rect 1x0.75 smd: 1(-1.173,0) 2(1.173,0)
  silkscreen extent -1.08,-0.8 0.9,0.8
"SOD-523_L1.2-W0.8-LS1.6-RD-1 NSK" [mm]
  rect 0.6x0.36 smd: 1(-0.635,0) 2(0.635,0)
  silkscreen extent -0.13,-0.13 -0.13,0.13
SOIC-8_L5.0-W4.0-P1.27-LS6.0-BL-EP2.0 [mm]
  oval 0.574x2.038 smd: 1(-1.905,-2.769) 2(-0.635,-2.769) 3(0.635,-2.769) 4(1.905,-2.769) 5(1.905,2.769) 6(0.635,2.769) 7(-0.635,2.769) 8(-1.905,2.769)
  rect 2x2 smd: 9(0,0)
  silkscreen extent -2.79,-2.92 2.53,1.52
SOT-23-3_L2.9-W1.3-P1.90-LS2.4-BR [mm]
  rect 1.25x0.7 smd: 1(1,-0.95) 2(1,0.95) 3(-1,0)
  silkscreen extent -0.73,-1.53 0.73,1.53
SOT-23-5_L3.0-W1.7-P0.95-LS2.8-BL [mm]
  rect 0.49x1.157 smd: 1(-0.95,-1.154) 2(0,-1.154) 3(0.95,-1.154)
  rect 0.49x1.175 smd: 4(0.95,1.154) 5(-0.95,1.154)
  silkscreen extent -1.8,-1.29 1.53,0.85
SW-SMD_4P-L4.2-W3.4-P2.15-LS4.5-TL [mm]
  rect 1.05x0.7 smd: 1(-2.1,1.075) 2(2.1,1.075) 3(-2.1,-1.075) 4(2.1,-1.075)
  silkscreen extent -2.2,-1.69 2.2,1.71
T527-BGA664 [mm]
  round 0.239 smd: A1(-8,8) A2(-7.5,8) A3(-7,8) A4(-6.5,8) A5(-6,8) A6(-5.5,8) A8(-4.5,8) A10(-3.5,8) A12(-2.5,8) A14(-1.5,8) A16(-0.5,8) A18(0.5,8) A20(1.5,8) A22(2.5,8) A24(3.5,8) A26(4.5,8) A28(5.5,8) A29(6,8) A30(6.5,8) A31(7,8) A32(7.5,8) A33(8,8) AA1(-8,-2) AA2(-7.5,-2) AA3(-7,-2) AA4(-6.5,-2) AA5(-6,-2) AA6(-5.5,-2) AA7(-5,-2) AA9(-4,-2) AA12(-2.5,-2) AA13(-2,-2) AA15(-1,-2) AA16(-0.5,-2) AA18(0.5,-2) AA19(1,-2) AA21(2,-2) AA22(2.5,-2) AA24(3.5,-2) AA26(4.5,-2) AA27(5,-2) AA28(5.5,-2) AA29(6,-2) AA30(6.5,-2) AA31(7,-2) AA32(7.5,-2) AA33(8,-2) AB2(-7.5,-2.5) AB3(-7,-2.5) AB9(-4,-2.5) AB10(-3.5,-2.5) AB11(-3,-2.5) AB12(-2.5,-2.5) AB13(-2,-2.5) AB14(-1.5,-2.5) AB15(-1,-2.5) AB17(0,-2.5) AB24(3.5,-2.5) AB32(7.5,-2.5) AB33(8,-2.5) AC1(-8,-3) AC2(-7.5,-3) AC3(-7,-3) AC4(-6.5,-3) AC5(-6,-3) AC6(-5.5,-3) AC7(-5,-3) AC9(-4,-3) AC15(-1,-3) AC17(0,-3) AC18(0.5,-3) AC19(1,-3) AC20(1.5,-3) AC22(2.5,-3) AC24(3.5,-3) AC26(4.5,-3) AC27(5,-3) AC28(5.5,-3) AC29(6,-3) AC30(6.5,-3) AC31(7,-3) AC32(7.5,-3) AC33(8,-3) AD1(-8,-3.5) AD2(-7.5,-3.5) AD9(-4,-3.5) AD11(-3,-3.5) AD13(-2,-3.5) AD14(-1.5,-3.5) AD15(-1,-3.5) AD20(1.5,-3.5) AD21(2,-3.5) AD22(2.5,-3.5) AD25(4,-3.5) AD32(7.5,-3.5) AD33(8,-3.5) AE1(-8,-4) AE2(-7.5,-4) AE3(-7,-4) AE4(-6.5,-4) AE5(-6,-4) AE6(-5.5,-4) AE7(-5,-4) AE9(-4,-4) AE11(-3,-4) AE12(-2.5,-4) AE13(-2,-4) AE14(-1.5,-4) AE16(-0.5,-4) AE18(0.5,-4) AE19(1,-4) AE20(1.5,-4) AE21(2,-4) AE22(2.5,-4) AE23(3,-4) AE24(3.5,-4) AE25(4,-4) AE26(4.5,-4) AE27(5,-4) AE28(5.5,-4) AE29(6,-4) AE30(6.5,-4) AE31(7,-4) AE32(7.5,-4) AE33(8,-4) AF1(-8,-4.5) AF2(-7.5,-4.5) AF32(7.5,-4.5) AF33(8,-4.5) AG1(-8,-5) AG2(-7.5,-5) AG3(-7,-5) AG4(-6.5,-5) AG5(-6,-5) AG6(-5.5,-5) AG7(-5,-5) AG9(-4,-5) AG11(-3,-5) AG13(-2,-5) AG15(-1,-5) AG17(0,-5) AG19(1,-5) AG21(2,-5) AG23(3,-5) AG25(4,-5) AG28(5.5,-5) AG29(6,-5) AG30(6.5,-5) AG31(7,-5) AG32(7.5,-5) AG33(8,-5) AH1(-8,-5.5) AH2(-7.5,-5.5) AH7(-5,-5.5) AH9(-4,-5.5) AH11(-3,-5.5) AH13(-2,-5.5) AH15(-1,-5.5) AH17(0,-5.5) AH19(1,-5.5) AH21(2,-5.5) AH23(3,-5.5) AH25(4,-5.5) AH27(5,-5.5) AH32(7.5,-5.5) AH33(8,-5.5) AJ1(-8,-6) AJ2(-7.5,-6) AJ3(-7,-6) AJ4(-6.5,-6) AJ5(-6,-6) AJ7(-5,-6) AJ9(-4,-6) AJ11(-3,-6) AJ13(-2,-6) AJ15(-1,-6) AJ17(0,-6) AJ19(1,-6) AJ21(2,-6) AJ23(3,-6) AJ25(4,-6) AJ27(5,-6) AJ30(6.5,-6) AJ31(7,-6) AJ32(7.5,-6) AJ33(8,-6) AK1(-8,-6.5) AK2(-7.5,-6.5) AK5(-6,-6.5) AK7(-5,-6.5) AK9(-4,-6.5) AK11(-3,-6.5) AK13(-2,-6.5) AK15(-1,-6.5) AK17(0,-6.5) AK19(1,-6.5) AK21(2,-6.5) AK23(3,-6.5) AK25(4,-6.5) AK27(5,-6.5) AK29(6,-6.5) AK32(7.5,-6.5) AK33(8,-6.5) AL1(-8,-7) AL2(-7.5,-7) AL3(-7,-7) AL5(-6,-7) AL7(-5,-7) AL9(-4,-7) AL11(-3,-7) AL12(-2.5,-7) AL13(-2,-7) AL14(-1.5,-7) AL15(-1,-7) AL16(-0.5,-7) AL17(0,-7) AL19(1,-7) AL21(2,-7) AL23(3,-7) AL25(4,-7) AL27(5,-7) AL29(6,-7) AL31(7,-7) AL32(7.5,-7) AL33(8,-7) AM1(-8,-7.5) AM2(-7.5,-7.5) AM3(-7,-7.5) AM4(-6.5,-7.5) AM5(-6,-7.5) AM6(-5.5,-7.5) AM7(-5,-7.5) AM8(-4.5,-7.5) AM9(-4,-7.5) AM10(-3.5,-7.5) AM11(-3,-7.5) AM12(-2.5,-7.5) AM13(-2,-7.5) AM14(-1.5,-7.5) AM15(-1,-7.5) AM16(-0.5,-7.5) AM17(0,-7.5) AM18(0.5,-7.5) AM19(1,-7.5) AM20(1.5,-7.5) AM21(2,-7.5) AM22(2.5,-7.5) AM23(3,-7.5) AM24(3.5,-7.5) AM25(4,-7.5) AM26(4.5,-7.5) AM27(5,-7.5) AM28(5.5,-7.5) AM29(6,-7.5) AM30(6.5,-7.5) AM31(7,-7.5) AM32(7.5,-7.5) AM33(8,-7.5) AN1(-8,-8) AN2(-7.5,-8) AN3(-7,-8) AN4(-6.5,-8) AN5(-6,-8) AN6(-5.5,-8) AN7(-5,-8) AN8(-4.5,-8) AN9(-4,-8) AN10(-3.5,-8) AN11(-3,-8) AN13(-2,-8) AN15(-1,-8) AN17(0,-8) AN18(0.5,-8) AN19(1,-8) AN20(1.5,-8) AN21(2,-8) AN22(2.5,-8) AN23(3,-8) AN24(3.5,-8) AN25(4,-8) AN26(4.5,-8) AN27(5,-8) AN28(5.5,-8) AN29(6,-8) AN30(6.5,-8) AN31(7,-8) AN32(7.5,-8) AN33(8,-8) B1(-8,7.5) B2(-7.5,7.5) B3(-7,7.5) B4(-6.5,7.5) B5(-6,7.5) B6(-5.5,7.5) B7(-5,7.5) B8(-4.5,7.5) B9(-4,7.5) B10(-3.5,7.5) B11(-3,7.5) B12(-2.5,7.5) B13(-2,7.5) B14(-1.5,7.5) B15(-1,7.5) B16(-0.5,7.5) B17(0,7.5) B18(0.5,7.5) B19(1,7.5) B20(1.5,7.5) B21(2,7.5) B22(2.5,7.5) B23(3,7.5) B24(3.5,7.5) B25(4,7.5) B26(4.5,7.5) B27(5,7.5) B28(5.5,7.5) B29(6,7.5) B30(6.5,7.5) B31(7,7.5) B32(7.5,7.5) B33(8,7.5) C1(-8,7) C2(-7.5,7) C3(-7,7) C4(-6.5,7) C6(-5.5,7) C7(-5,7) C8(-4.5,7) C9(-4,7) C10(-3.5,7) C11(-3,7) C12(-2.5,7) C13(-2,7) C14(-1.5,7) C15(-1,7) C16(-0.5,7) C17(0,7) C18(0.5,7) C19(1,7) C20(1.5,7) C21(2,7) C22(2.5,7) C23(3,7) C24(3.5,7) C25(4,7) C26(4.5,7) C27(5,7) C28(5.5,7) C29(6,7) C30(6.5,7) C31(7,7) C32(7.5,7) C33(8,7) D1(-8,6.5) D2(-7.5,6.5) D6(-5.5,6.5) D8(-4.5,6.5) D10(-3.5,6.5) D12(-2.5,6.5) D14(-1.5,6.5) D16(-0.5,6.5) D18(0.5,6.5) D20(1.5,6.5) D22(2.5,6.5) D24(3.5,6.5) D26(4.5,6.5) D28(5.5,6.5) D32(7.5,6.5) D33(8,6.5) E1(-8,6) E2(-7.5,6) E3(-7,6) E4(-6.5,6) E5(-6,6) E6(-5.5,6) E8(-4.5,6) E10(-3.5,6) E12(-2.5,6) E14(-1.5,6) E16(-0.5,6) E18(0.5,6) E20(1.5,6) E22(2.5,6) E24(3.5,6) E26(4.5,6) E28(5.5,6) E29(6,6) E30(6.5,6) E31(7,6) E32(7.5,6) E33(8,6) F1(-8,5.5) F2(-7.5,5.5) F6(-5.5,5.5) F8(-4.5,5.5) F10(-3.5,5.5) F12(-2.5,5.5) F14(-1.5,5.5) F16(-0.5,5.5) F18(0.5,5.5) F20(1.5,5.5) F22(2.5,5.5) F24(3.5,5.5) F26(4.5,5.5) F28(5.5,5.5) F32(7.5,5.5) F33(8,5.5) G1(-8,5) G2(-7.5,5) G3(-7,5) G4(-6.5,5) G5(-6,5) G6(-5.5,5) G8(-4.5,5) G10(-3.5,5) G12(-2.5,5) G14(-1.5,5) G16(-0.5,5) G18(0.5,5) G20(1.5,5) G22(2.5,5) G24(3.5,5) G26(4.5,5) G28(5.5,5) G29(6,5) G30(6.5,5) G31(7,5) G32(7.5,5) G33(8,5) H2(-7.5,4.5) H3(-7,4.5) H24(3.5,4.5) H31(7,4.5) H32(7.5,4.5) J1(-8,4) J2(-7.5,4) J3(-7,4) J4(-6.5,4) J5(-6,4) J6(-5.5,4) J7(-5,4) J9(-4,4) J10(-3.5,4) J12(-2.5,4) J13(-2,4) J15(-1,4) J16(-0.5,4) J17(0,4) J18(0.5,4) J19(1,4) J21(2,4) J22(2.5,4) J23(3,4) J26(4.5,4) J28(5.5,4) J29(6,4) J30(6.5,4) J31(7,4) J32(7.5,4) J33(8,4) K2(-7.5,3.5) K3(-7,3.5) K9(-4,3.5) K10(-3.5,3.5) K11(-3,3.5) K12(-2.5,3.5) K13(-2,3.5) K15(-1,3.5) K16(-0.5,3.5) K19(1,3.5) K21(2,3.5) K22(2.5,3.5) K24(3.5,3.5) K25(4,3.5) K26(4.5,3.5) K31(7,3.5) K32(7.5,3.5) L1(-8,3) L2(-7.5,3) L3(-7,3) L4(-6.5,3) L5(-6,3) L6(-5.5,3) L7(-5,3) L9(-4,3) L10(-3.5,3) L12(-2.5,3) L13(-2,3) L15(-1,3) L16(-0.5,3) L17(0,3) L18(0.5,3) L19(1,3) L21(2,3) L22(2.5,3) L24(3.5,3) L26(4.5,3) L27(5,3) L28(5.5,3) L29(6,3) L30(6.5,3) L31(7,3) L32(7.5,3) L33(8,3) M2(-7.5,2.5) M3(-7,2.5) M10(-3.5,2.5) M13(-2,2.5) M16(-0.5,2.5) M18(0.5,2.5) M19(1,2.5) M21(2,2.5) M22(2.5,2.5) M31(7,2.5) M32(7.5,2.5) N1(-8,2) N2(-7.5,2) N3(-7,2) N4(-6.5,2) N5(-6,2) N6(-5.5,2) N7(-5,2) N9(-4,2) N10(-3.5,2) N12(-2.5,2) N13(-2,2) N15(-1,2) N18(0.5,2) N19(1,2) N21(2,2) N22(2.5,2) N24(3.5,2) N26(4.5,2) N27(5,2) N28(5.5,2) N29(6,2) N30(6.5,2) N31(7,2) N32(7.5,2) N33(8,2) P2(-7.5,1.5) P3(-7,1.5) P9(-4,1.5) P11(-3,1.5) P13(-2,1.5) P16(-0.5,1.5) P18(0.5,1.5) P19(1,1.5) P21(2,1.5) P22(2.5,1.5) P24(3.5,1.5) P31(7,1.5) P32(7.5,1.5) R1(-8,1) R2(-7.5,1) R3(-7,1) R4(-6.5,1) R5(-6,1) R6(-5.5,1) R7(-5,1) R11(-3,1) R13(-2,1) R15(-1,1) R17(0,1) R18(0.5,1) R19(1,1) R22(2.5,1) R24(3.5,1) R26(4.5,1) R27(5,1) R28(5.5,1) R29(6,1) R30(6.5,1) R31(7,1) R32(7.5,1) R33(8,1) T2(-7.5,0.5) T3(-7,0.5) T9(-4,0.5) T11(-3,0.5) T13(-2,0.5) T15(-1,0.5) T16(-0.5,0.5) T18(0.5,0.5) T19(1,0.5) T21(2,0.5) T22(2.5,0.5) T24(3.5,0.5) T31(7,0.5) T32(7.5,0.5) U1(-8,0) U2(-7.5,0) U3(-7,0) U4(-6.5,0) U5(-6,0) U6(-5.5,0) U7(-5,0) U8(-4.5,0) U10(-3.5,0) U12(-2.5,0) U13(-2,0) U14(-1.5,0) U16(-0.5,0) U18(0.5,0) U19(1,0) U21(2,0) U22(2.5,0) U25(4,0) U26(4.5,0) U27(5,0) U28(5.5,0) U29(6,0) U30(6.5,0) U31(7,0) U32(7.5,0) U33(8,0) V2(-7.5,-0.5) V3(-7,-0.5) V18(0.5,-0.5) V19(1,-0.5) V31(7,-0.5) V32(7.5,-0.5) W1(-8,-1) W2(-7.5,-1) W3(-7,-1) W4(-6.5,-1) W5(-6,-1) W6(-5.5,-1) W7(-5,-1) W9(-4,-1) W10(-3.5,-1) W12(-2.5,-1) W13(-2,-1) W15(-1,-1) W16(-0.5,-1) W19(1,-1) W21(2,-1) W22(2.5,-1) W23(3,-1) W24(3.5,-1) W25(4,-1) W27(5,-1) W28(5.5,-1) W29(6,-1) W30(6.5,-1) W31(7,-1) W32(7.5,-1) W33(8,-1) Y2(-7.5,-1.5) Y3(-7,-1.5) Y9(-4,-1.5) Y10(-3.5,-1.5) Y12(-2.5,-1.5) Y13(-2,-1.5) Y15(-1,-1.5) Y18(0.5,-1.5) Y19(1,-1.5) Y21(2,-1.5) Y22(2.5,-1.5) Y23(3,-1.5) Y24(3.5,-1.5) Y26(4.5,-1.5) Y31(7,-1.5) Y32(7.5,-1.5)
  silkscreen extent -9.26,-8.55 8.55,9.13
TFT_1.14寸_0.7MM-13P [mm]
  oval 4x0.35 smd: 1(2.65,4.2) 2(2.65,3.5) 3(2.65,2.8) 4(2.65,2.1) 5(2.65,1.4) 6(2.65,0.7) 7(2.65,0) 8(2.65,-0.7) 9(2.65,-1.4) 10(2.65,-2.1) 11(2.65,-2.8) 12(2.65,-3.5) 13(2.65,-4.2)
  silkscreen extent -15.5,-8.8 15.5,8.8
USB-A-TH_XUNPU_USB-303WSD-BRY [mm]
  round 1.1 hole 0.7: 1(-3.5,-1.35) 2(-1,-1.35) 3(1,-1.35) 4(3.5,-1.35) 5(4,0.15) 6(2,0.15) 7(0,0.15) 8(-2,0.15) 9(-4,0.15) 10(-3.5,1.85) 11(-1,1.85) 12(1,1.85) 13(3.5,1.85) 14(4,3.35) 15(2,3.35) 16(0,3.35) 17(-2,3.35) 18(-4,3.35)
  round 3.2 hole 2.4: 19(6.57,-3.35) 20(6.57,2.33) 21(-6.57,2.33) 22(-6.57,-3.35)
  silkscreen extent -7.26,-12.97 7.19,4.7
USB-C-SMD_TYPEC-304-BCP16-1 [mm]
  oval 1x2.1 hole 0.6 slot 1.7 at 90 deg: 12(-4.32,1.633) 13(4.32,1.633)
  oval 1x1.6 hole 0.6 slot 1.2 at 90 deg: 14(-4.32,-2.547) 15(4.32,-2.547)
  rect 0.55x1.45 smd: A1B12(-3.225,2.547) A4B9(-2.45,2.547) B1A12(3.225,2.547) B4A9(2.45,2.547)
  rect 0.3x1.45 smd: A5(-1.25,2.547) A6(-0.25,2.547) A7(0.25,2.547) A8(1.25,2.547) B5(1.75,2.547) B6(0.75,2.547) B7(-0.75,2.547) B8(-1.75,2.547)
  Multi-Layer board cut-out: -3.215,1.102 -3.169,0.943 -3.051,0.826 -2.89,0.784 -2.729,0.826 -2.611,0.943 -2.565,1.102 -2.565,1.102 -2.611,1.262 -2.729,1.378 -2.89,1.421 -3.051,1.379 -3.169,1.262 -3.215,1.102
  Multi-Layer board cut-out: 2.565,1.102 2.611,0.943 2.729,0.826 2.89,0.784 3.051,0.826 3.169,0.943 3.215,1.102 3.215,1.102 3.169,1.262 3.051,1.378 2.89,1.421 2.729,1.379 2.611,1.262 2.565,1.102
  Multi-Layer keep-out circle w0.254: c-2.89,1.102 r0.325
  Multi-Layer keep-out circle w0.254: c2.89,1.102 r0.325
  silkscreen extent -4.4,-5.15 4.4,0.41
WQFN-40_L5.0-W5.0-P0.4-BL-EP [mm]
  oval 0.2x0.8 smd: 1(-1.801,-2.499) 2(-1.4,-2.499) 3(-1.001,-2.499) 4(-0.599,-2.499) 5(-0.201,-2.499) 6(0.201,-2.499) 7(0.599,-2.499) 8(1.001,-2.499) 9(1.4,-2.499) 10(1.801,-2.499) 21(1.801,2.499) 22(1.4,2.499) 23(1.001,2.499) 24(0.599,2.499) 25(0.201,2.499) 26(-0.201,2.499) 27(-0.599,2.499) 28(-1.001,2.499) 29(-1.4,2.499) 30(-1.801,2.499)
  oval 0.8x0.2 smd: 11(2.499,-1.801) 12(2.499,-1.4) 13(2.499,-1.001) 14(2.499,-0.599) 15(2.499,-0.201) 16(2.499,0.201) 17(2.499,0.599) 18(2.499,1.001) 19(2.499,1.4) 20(2.499,1.801) 31(-2.499,1.801) 32(-2.499,1.4) 33(-2.499,1.001) 34(-2.499,0.599) 35(-2.499,0.201) 36(-2.499,-0.201) 37(-2.499,-0.599) 38(-2.499,-1.001) 39(-2.499,-1.4) 40(-2.499,-1.801)
  rect 3.8x3.8 smd: 41(0,0)
  silkscreen extent -2.7,-3.35 2.7,2.7

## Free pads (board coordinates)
  round 196.85 hole 129.92: 54(3462,3578) 54(3471,6294) 54(5737,6292) 54(7163,6288) 54(7169,3579)

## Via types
v1: diameter 15.75, hole 11.8, Top Layer to Bottom Layer, 496 vias
v2: diameter 15.7, hole 11.8, Top Layer to Bottom Layer, 335 vias
v3: diameter 15.75, hole 11.81, Top Layer to Bottom Layer, 279 vias
v4: diameter 24, hole 12, Top Layer to Bottom Layer, 9 vias

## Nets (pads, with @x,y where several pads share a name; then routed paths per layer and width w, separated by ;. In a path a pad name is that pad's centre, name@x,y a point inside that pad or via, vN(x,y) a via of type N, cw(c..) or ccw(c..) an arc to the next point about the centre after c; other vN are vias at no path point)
323-ALDO1: C69.1 U5.15 | length 32.4
  Top Layer w8: U5.15@4019.34,5098.08 4019.34,5070.16 C69.1@4022.5,5067
323-DCDC1/2: C72.2 C74.2 C80.2 C81.2 L6.2 L7.2 U14.T19 U14.T21 U14.T22 U14.U18 U14.U19 U14.U21 U14.U22 | length 430
  Top Layer w8: v2(5748,5277) 5748,5296 v2(5747,5297) v2(5767,5297) ; U14.U21@5766.98,5276.73 v2(5767,5297) ; U14.U18@5766.98,5335.78 U14.U19@5766.98,5316.1 v2(5767,5297) ; U14.T21@5786.67,5276.73 5787,5277.06 5787,5297 ; U14.T19@5786.67,5316.1 5787,5315.76 5787,5297 ; v2(5767,5297) 5787,5297
  Bottom Layer w10: 5745.5,5257 5748,5259.5 v2(5748,5277) 5748,5296 v2(5747,5297) v2(5767,5297) ; 5766.98,5236.52 v2(5766.98,5257.04) ; 5809,5237 5808.5,5236.5 5787,5236.5 5787,5256.71 v2(5786.67,5257.04) ; v2(5766.98,5257.04) v2(5767,5297) ; v2(5766.98,5257.04) v2(5786.67,5257.04) ; v2(5767,5297) 5767,5305.5 5764,5308.5 5786,5308.5 5786.67,5307.83 v2(5786.67,5257.04)
  other v1: 4216,5076 4236.59,5076 4213,5104 4213,5132.37 4213,5154.8 4213,5180.01 4213,5206.33 4213,5232.09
